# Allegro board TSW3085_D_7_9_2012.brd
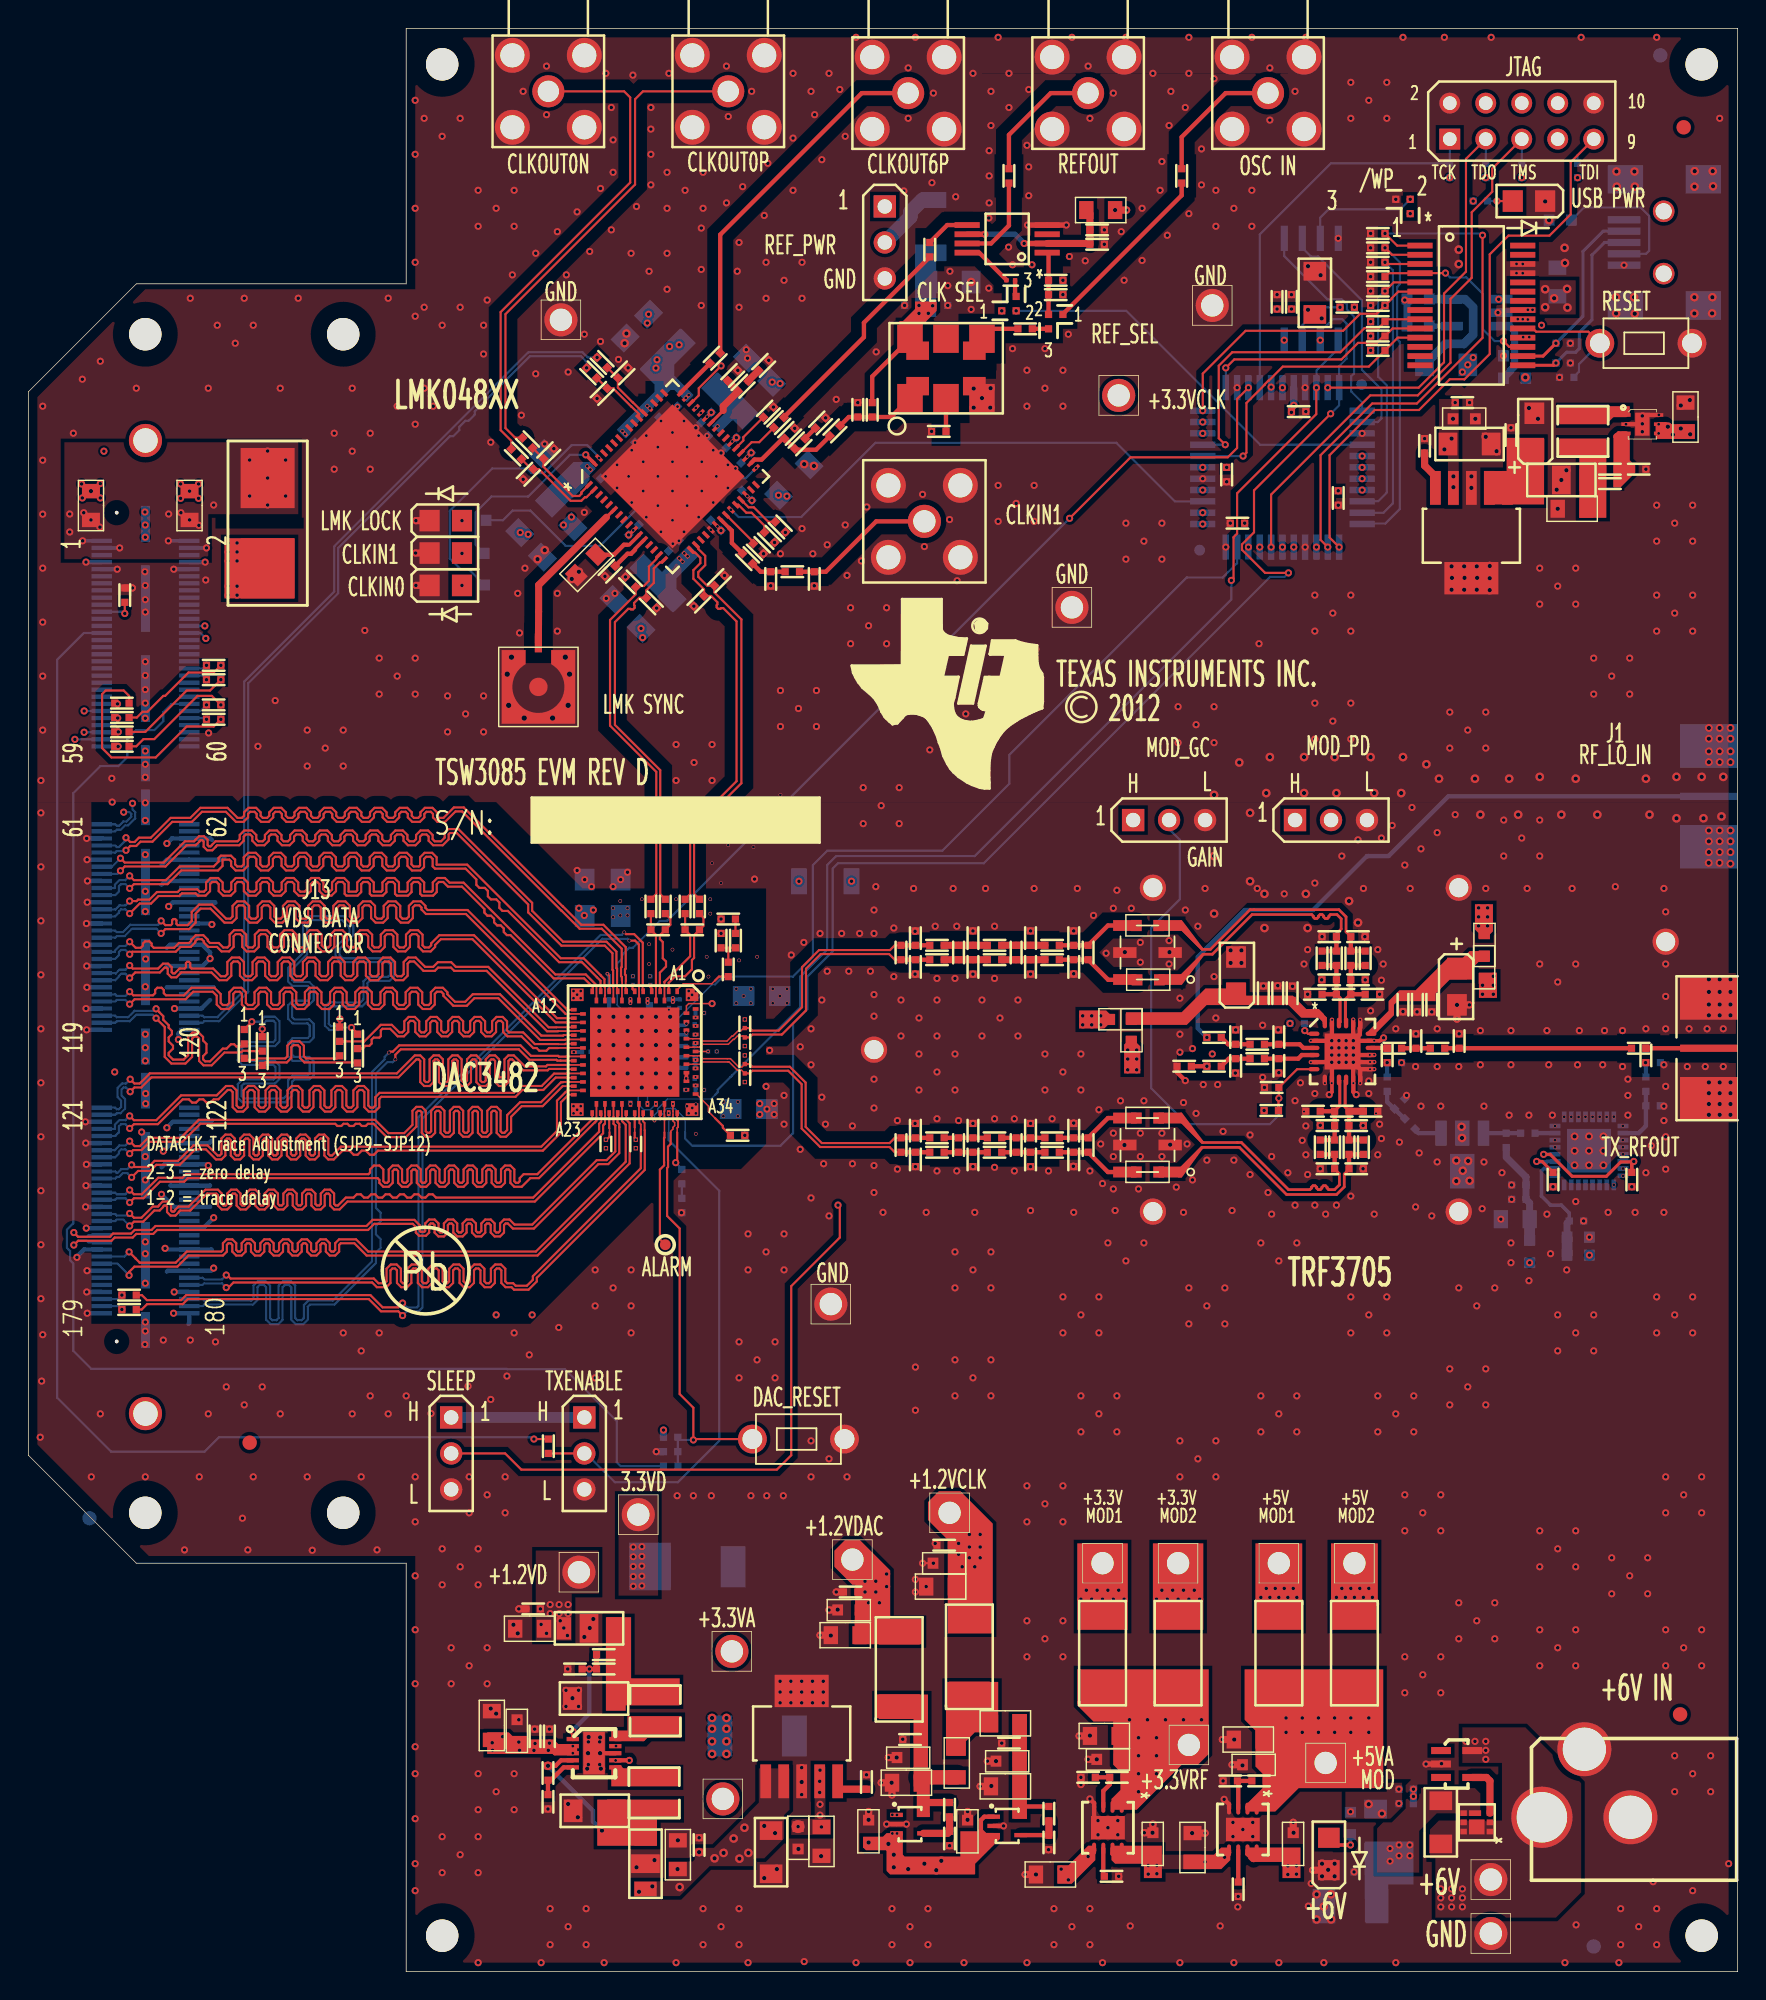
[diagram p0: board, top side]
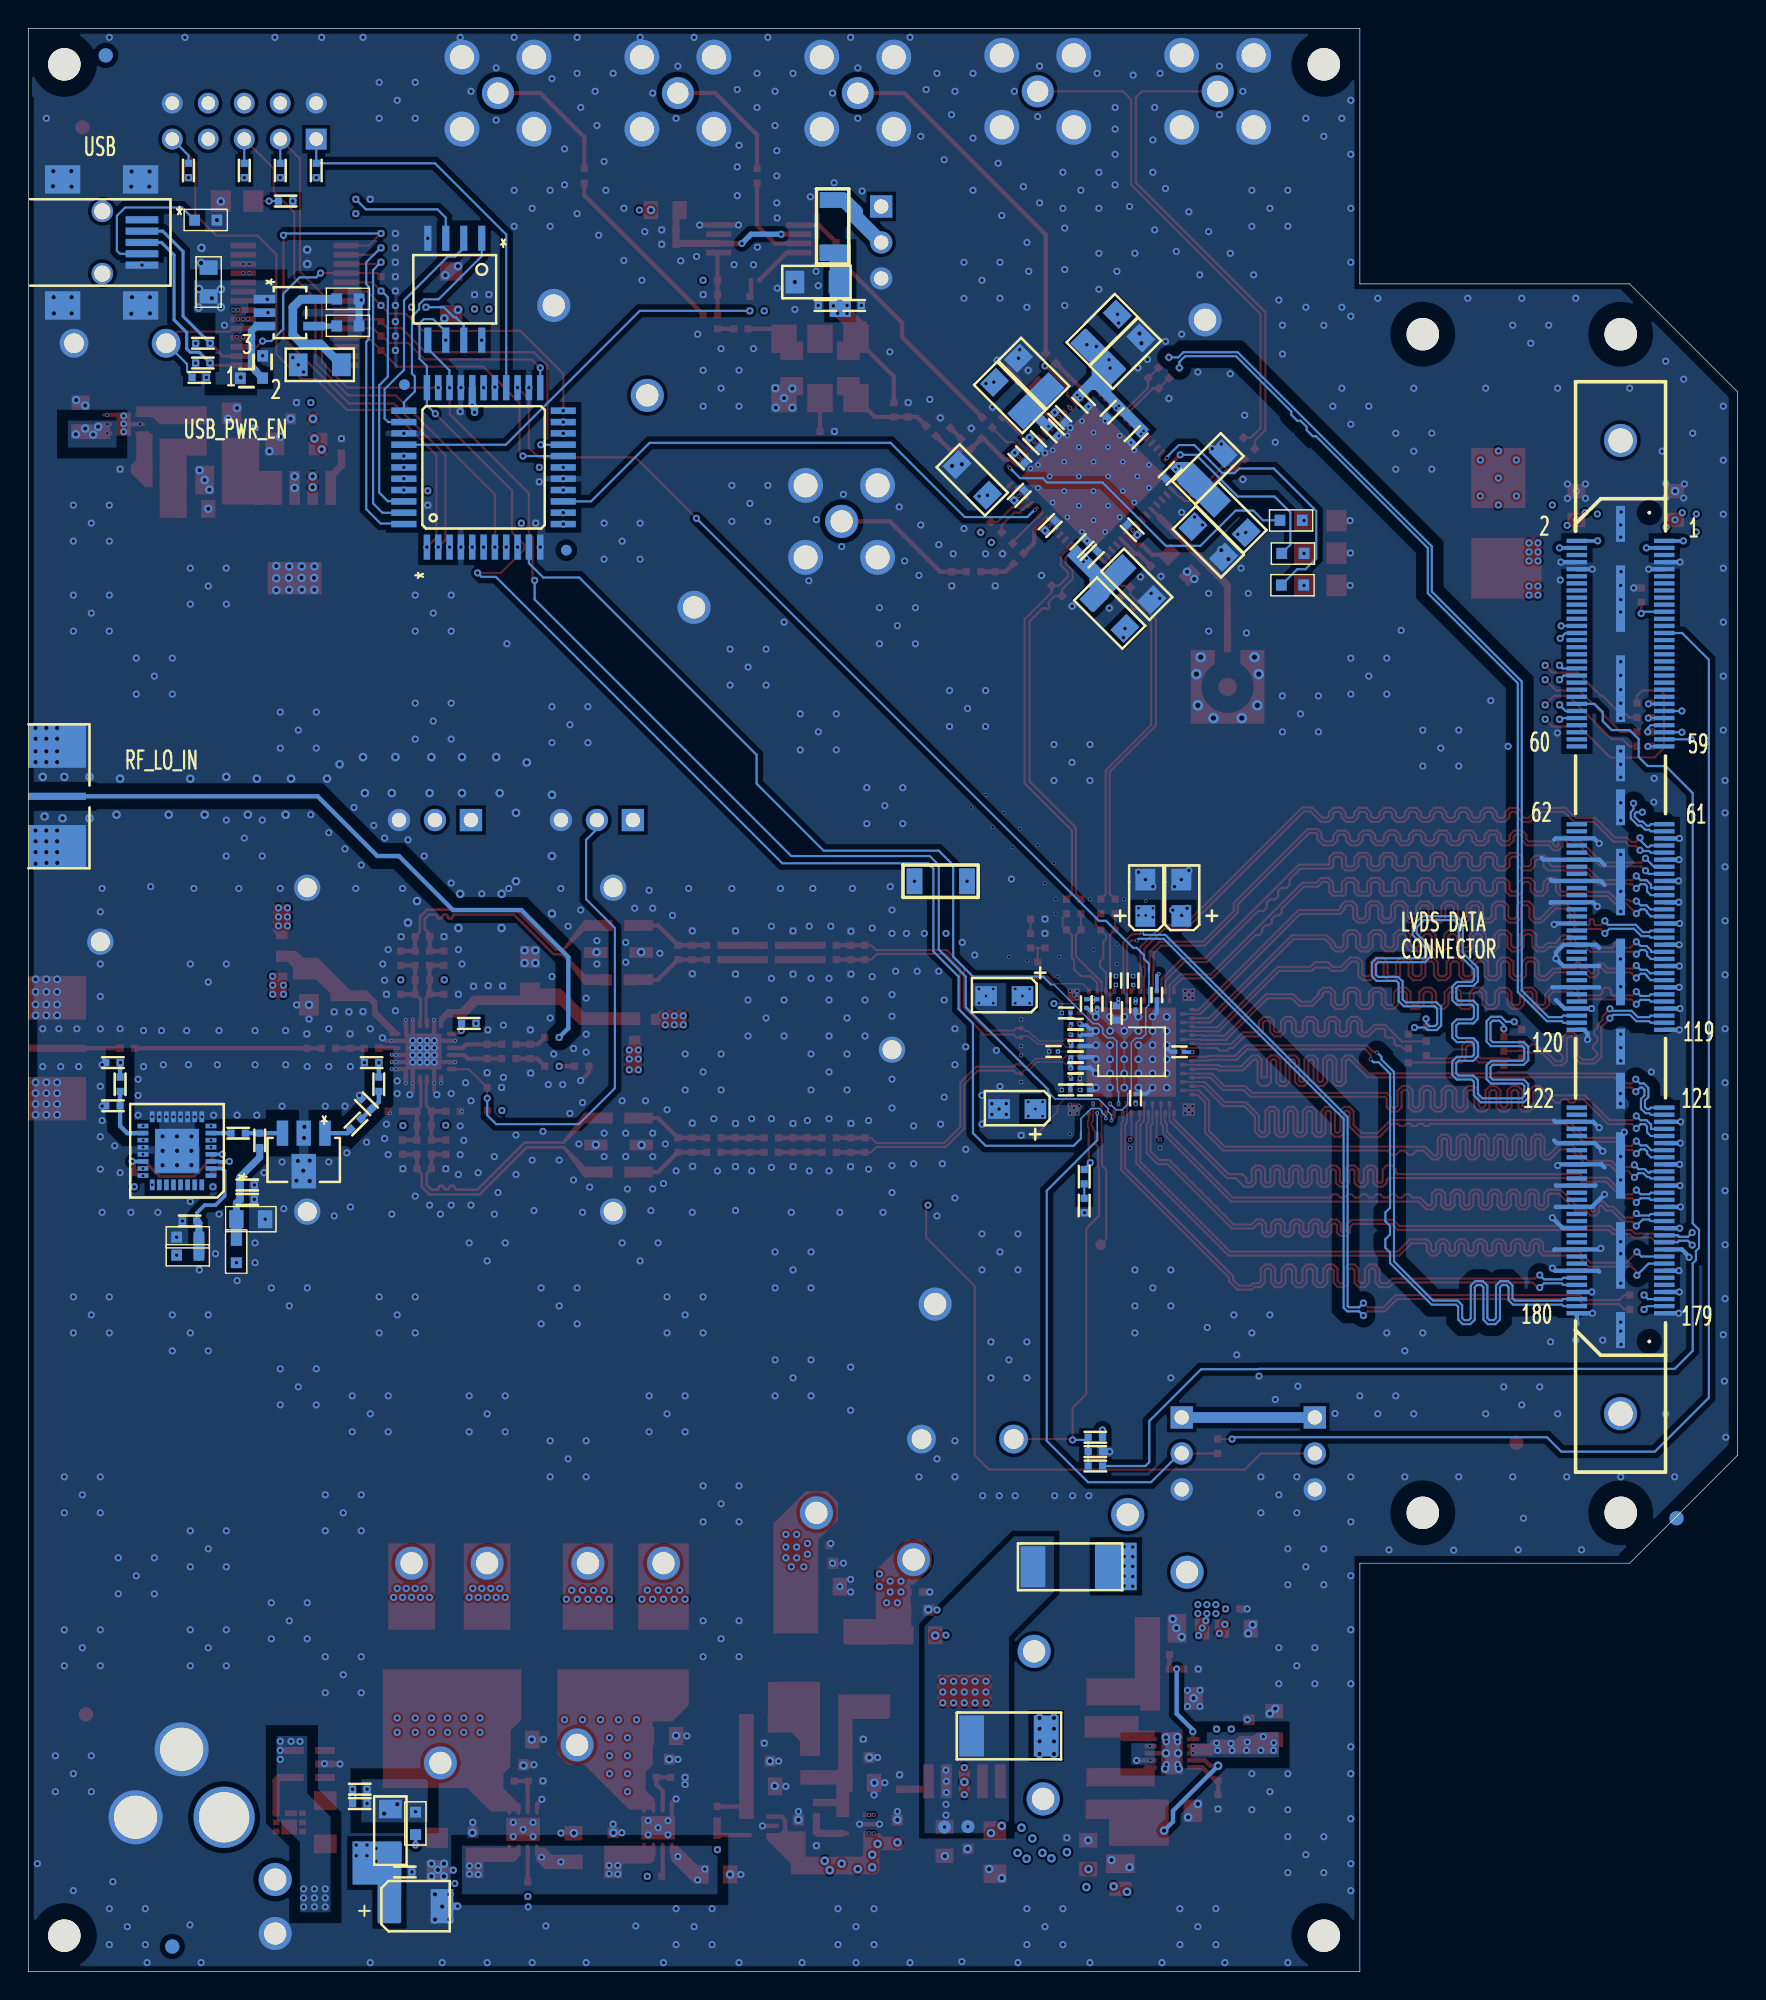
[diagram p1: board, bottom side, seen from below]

Outline 120.65 x 137.16 mm; copper layers: TOP, L2_GND, L3_PWR, L4_GND, L5_GND, L6_PWR, L7_GND, BOTTOM. Coordinates in mm from the lower left corner of the outline.
Outline path: 0,111.51 0,36.45 7.62,28.83 26.67,28.83 26.67,0 120.65,0 120.65,137.16 26.67,137.16 26.67,119.13 7.62,119.13 0,111.51

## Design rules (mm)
net group CLKIN0: nets CLKIN0N CLKIN0P
net group CLKOUT0: nets CLKOUT0N CLKOUT0P
net group CLKOUT_0: nets CLKOUT_0N CLKOUT_0P
net group DA0: nets DA0N DA0P
net group DA1: nets DA1N DA1P
net group DA2: nets DA2N DA2P
net group DA3: nets DA3N DA3P
net group DA4: nets DA4N DA4P
net group DA5: nets DA5N DA5P
net group DA6: nets DA6N DA6P
net group DA7: nets DA7N DA7P
net group DA8: nets DA8N DA8P
net group DA9: nets DA9N DA9P
net group DA10: nets DA10N DA10P
net group DA11: nets DA11N DA11P
net group DA12: nets DA12N DA12P
net group DA13: nets DA13N DA13P
net group DA14: nets DA14N DA14P
net group DA15: nets DA15N DA15P
net group DATACLK: nets DATACLKN DATACLKP
net group DATACLK-: nets DATACLK-N DATACLK-P
net group DIFFPAIR0: nets IOUTC1 IOUTC2
net group DIFFPAIR1: nets CLKOUT8N CLKOUT8P
net group DIFFPAIR2: nets TXCCLKN TXCCLKP
net group DIFFPAIR3: nets DCLKN DCLKP
net group DP2: nets IOUTB1 IOUTB2
net group DP4: nets IN-1 IP-1
net group DP5: nets FIFO_OSTR FIFO_OSTRC
net group DP7: nets DACCLK DACCLKC
net group DP8: nets IN_1 IP_1
net group DP12: nets QN-1 QP-1
net group DP14: nets QN_1 QP_1
net group DP18: nets DAC_FIFO_OSTR DAC_FIFO_OSTRC
net group FIFO_ISTR: nets FIFO_ISTRN FIFO_ISTRP
net group FPGA_CLKOUT: nets FPGA_CLKOUTN FPGA_CLKOUTP
net group PARITY: nets PARITYN PARITYP
net group PRI_DAC_CLK: nets PRI_DAC_CLKN PRI_DAC_CLKP
net group SYNC: nets SYNCN SYNCP

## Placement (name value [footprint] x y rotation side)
C1  .01uF  [0402]  46.36 75.06 270 top
C2  .01uF  [0402]  47.37 75.06 270 top
C3  .01uF  [0402]  43.94 75.31 90 top
C4  .01uF  [0402]  44.96 75.31 90 top
C5  .22uF  [0201]  46.74 63.78 180 bottom
C6  .22uF  [0201]  46.08 62.23 180 bottom
C7  0.01uF  [0603]  98.09 116.15 180 bottom
C8  4.7uF  [0603]  98.09 118.06 180 bottom
C9  10uF  [0805]  107.92 119.25 90 bottom
C13  10uF  [TANT_A]  51.77 68.86 0 bottom
C15  .22uF  [0201]  48.29 64.95 0 bottom
C17  .22uF  [0201]  47.4 67.67 0 bottom
C19  .22uF  [0201]  47.4 62.23 0 bottom
C20  .22uF  [0201]  46.74 65.33 180 bottom
C21  .22uF  [0201]  46.74 66.88 180 bottom
C22  .22uF  [0201]  46.74 64.54 180 bottom
C23  .22uF  [0201]  46.74 66.12 180 bottom
C24  .22uF  [0201]  46.74 63.02 180 bottom
C25  .22uF  [0201]  42.67 69.95 90 bottom
C26  .22uF  [0201]  41 68.94 270 bottom
C27  .22uF  [0201]  42.88 58.42 270 top
C29  .22uF  [0201]  40.77 58.42 270 top
C30  10uF  [TANT_A]  39.27 75.79 90 bottom
C34  .1uF  [0402]  49.28 74.3 180 top
C35  1000pF  [0402]  48.89 72.9 90 top
C36  .1uF  [0402]  43.84 67.54 270 bottom
C38  .22uF  [0201]  43.89 69.95 90 bottom
C40  10uF  [TANT_A]  41.81 75.79 90 bottom
C41  .22uF  [0201]  42.49 68.2 270 bottom
C42  .22uF  [0201]  42.49 61.65 90 bottom
C43  .22uF  [0201]  39.4 64.92 0 bottom
C47  1000pF  [0402]  45.21 36.7 180 bottom
C48  .1uF  [0201]  45.97 68.33 270 bottom
C49  .22uF  [0201]  45.21 68.33 270 bottom
C50  1000pF  [0402]  108.46 112.52 180 bottom
C52  .1uF  [0402]  40.97 98.76 225 top
C53  10uF  [TANT_A]  50.85 60.88 0 bottom
C59  10uF  [0805]  39.4 99.29 225 top
C60  .1uF  [0402]  52.88 109.25 225 top
C63  10uF  [1206]  65.02 119.25 0 bottom
C64  100pF  [0402]  62.23 117.6 180 bottom
C65  .1uF  [0402]  64.52 117.6 0 bottom
C72  10uF  [1206]  101.73 107.82 0 top
C75  .01uF  [0402]  101.35 110.74 0 top
C76  1uF  [0603]  101.35 109.6 0 top
C77  .1uF  [0402]  52.15 109.98 225 top
C78  .1uF  [0402]  51.44 100.53 135 top
C79  .1uF  [0402]  50.67 99.82 135 top
C80  .1uF  [0402]  42.82 101.85 45 bottom
C81  .1uF  [0402]  48.44 102.16 135 bottom
C82  .1uF  [0402]  50.57 106.76 225 bottom
C83  .1uF  [0402]  47.75 109.6 225 bottom
C84  .1uF  [0402]  50.62 104.29 135 bottom
C85  4.7uF  [0402]  49.71 108 45 bottom
C86  .1uF  [0402]  48.26 108.66 225 bottom
C87  .1uF  [0402]  40.13 105.66 315 bottom
C88  .1uF  [0402]  45.47 100 135 bottom
C89  .1uF  [0402]  42.55 108.2 315 bottom
C90  .1uF  [0402]  44.25 109.98 315 bottom
C95  47pF  [0402]  108.46 114.94 0 bottom
C96  47pF  [0402]  108.46 113.54 0 bottom
C97  .1uF  [0402]  95.12 119.63 180 top
C99  .1uF  [0402]  46.08 110.74 225 bottom
C100  .1uF  [0402]  52.98 102.06 135 top
C101  .1uF  [0402]  52.22 101.32 135 top
C102  .1uF  [0402]  46.2 100.74 135 bottom
C107  8.2pF  [0402]  49.81 112.75 45 top
C110  100pF  [0402]  105.08 55.52 180 bottom
C111  1uF  [0603]  34.49 16.99 90 top
C112  .1uF  [0402]  35.76 16.74 90 top
C113  .1uF  [0402]  76.58 6.73 0 top
C114  1uF  [0603]  79.38 9.02 90 top
C115  1uF  [0603]  76.2 14.99 180 top
C117  .1uF  [0402]  89.53 110.11 180 top
C119  .1uF  [0402]  85.39 5.69 270 top
C120  1uF  [0603]  89.28 9.02 90 top
C121  .5pF  [0402]  85.22 65.84 270 top
C122  .5pF  [0402]  88.27 65.84 270 top
C125  1.0pF  [0402]  92.96 68.99 0 top
C126  1.0pF  [0402]  92.84 60.73 0 top
C127  1500pF  [0402]  50.55 111.99 45 top
C128  10uF  [1206]  37.36 100.91 225 bottom
C131  .5pF  [0402]  88.27 64.06 90 top
C132  .5pF  [0402]  85.22 64.06 90 top
C133  10uF  [0805]  45.85 8.25 90 top
C134  10uF  [0805]  35.38 24.21 180 top
C135  .1uF  [0402]  84.58 105.79 90 top
C138  .1uF  [0402]  85.47 102.23 0 top
C139  .1uF  [0402]  92.46 104.14 90 top
C143  10uF  [0805]  4.42 103.48 90 top
C144  10uF  [0805]  11.38 103.48 90 top
C145  10uF  [0805]  55.98 9.19 270 top
C146  10uF  [0805]  61.98 13.34 180 top
C147  10uF  [0805]  57.66 23.75 180 top
C148  10uF  [0805]  64.39 27.18 180 top
C149  10uF  [0805]  68.96 13.08 180 top
C150  10uF  [0805]  72.14 6.86 180 top
C152  47uF  [TANT_B]  93.32 4.62 180 bottom
C153  .1uF  [0402]  93.95 7.04 180 bottom
C154  1uF  [0402]  97.38 11.86 0 bottom
C155  .01uF  [0402]  97.38 12.88 0 bottom
C156  .2pF  [0402]  97.94 65.56 270 top
C157  .5pF  [0402]  100.99 65.56 270 top
C161  10uF  [0805]  32.72 17.37 90 top
C162  .01uF  [0402]  59.16 13.51 90 top
C163  2.2uF  [1206]  52.43 8.43 270 top
C164  1uF  [0603]  54.33 9.45 270 top
C165  22uF  [1206]  39.98 11.35 180 top
C166  33pF  [0402]  40.49 21.36 180 top
C167  22uF  [1206]  39.93 19.28 180 top
C169  2.2uF  [0603]  59.31 9.91 90 top
C170  1uF  [0603]  57.91 25.53 180 top
C171  10uF  [0805]  75.95 16.64 180 top
C172  10uF  [0805]  82.17 8.76 90 top
C173  10uF  [0805]  86.11 16.38 180 top
C174  1uF  [0603]  86.49 14.61 180 top
C175  1000pF  [0402]  109.4 52.98 0 bottom
C176  1uF  [0603]  109.4 51.84 0 bottom
C177  .1uF  [0402]  54.56 107.92 45 top
C178  10uF  [1206]  54.03 105.28 45 bottom
C179  10uF  [1206]  37.39 106.07 135 bottom
C180  10uF  [1206]  43.21 114.22 135 bottom
C181  10uF  [1206]  42.42 97.92 225 bottom
C182  .1uF  [0402]  89.15 117.98 90 top
C184  3.3pF  [0402]  65.66 71.81 270 top
C185  3.3pF  [0402]  61.59 71.81 270 top
C186  3.3pF  [0402]  69.72 71.81 270 top
C187  100pF  [0402]  87.88 62.41 0 top
C190  3.3pF  [0402]  74.8 71.81 270 top
C191  CAP NP_1  [0402]  62.61 70.79 270 top
C192  CAP NP_1  [0402]  66.68 70.79 270 top
C193  CAP NP_1  [0402]  70.74 70.79 270 top
C194  CAP NP_1  [0402]  73.79 70.79 270 top
C195  CAP NP_1  [0402]  73.79 72.82 270 top
C196  CAP NP_1  [0402]  62.61 72.82 270 top
C197  CAP NP_1  [0402]  66.68 72.82 270 top
C198  CAP NP_1  [0402]  70.74 72.82 270 top
C199  CAP NP_1  [0402]  73.79 57.45 90 top
C200  CAP NP_1  [0402]  66.68 57.45 90 top
C204  3.3pF  [0402]  61.59 58.47 90 top
C205  3.3pF  [0402]  65.66 58.47 90 top
C206  3.3pF  [0402]  69.72 58.47 90 top
C214  1uF  [0402]  94.36 71.4 270 top
C215  .01uF  [0402]  98.55 107.82 90 top
C216  CAP NP_1  [0402]  62.61 57.45 90 top
C217  CAP NP_1  [0402]  70.74 57.45 90 top
C218  CAP NP_1  [0402]  73.79 59.49 90 top
C219  CAP NP_1  [0402]  62.61 59.49 90 top
C220  CAP NP_1  [0402]  66.68 59.49 90 top
C221  CAP NP_1  [0402]  70.74 59.49 90 top
C222  3.3pF  [0402]  74.8 58.47 90 top
C227  1uF  [0402]  91.31 71.4 270 top
C228  1uF  [0402]  94.23 58.32 90 top
C229  1uF  [0402]  91.19 58.32 90 top
C233  .01uF  [0402]  35.51 25.6 180 top
C234  .01uF  [0402]  47.35 9.07 90 top
C237  .01uF  [0402]  36.78 16.74 90 top
C238  1uF  [0603]  64.64 28.83 180 top
C240  2.2uF  [0603]  66.29 9.91 90 top
C242  .01uF  [0402]  64.52 30.1 180 top
C243  .01uF  [0402]  57.91 26.8 180 top
C244  1uF  [0603]  62.1 15.11 180 top
C245  .01uF  [0402]  62.1 16.38 180 top
C246  1uF  [0603]  69.09 14.86 180 top
C247  .01uF  [0402]  69.09 16.13 180 top
C249  20pF  [0402]  105.71 59.18 180 bottom
C250  .1uF  [0402]  88.14 117.98 90 top
C251  .1uF  [0402]  105.08 54.51 180 bottom
C252  3.3pF  [0402]  89.2 69.19 90 top
C253  .1uF  [0402]  88.19 69.19 90 top
C254  .1uF  [0402]  98.04 68.12 270 top
C255  3.3pF  [0402]  97.03 68.12 270 top
C256  2.2uF  [0805]  104.95 53.11 180 bottom
C257  20pF  [0402]  97.43 59.92 135 bottom
C258  6.8pF  [0402]  96.55 65.18 0 top
C259  47pF  [0402]  83.82 63.91 0 top
C260  47pF  [0402]  83.82 65.94 0 top
C288  1000pF  [0402]  87.17 69.19 90 top
C289  1000pF  [0402]  99.06 68.12 270 top
C290  4.7uF  [TANT_A]  85.24 70.33 90 top
C291  4.7uF  [TANT_A]  100.84 69.52 270 top
C298  10uF  [1206]  49.68 112.8 45 bottom
C299  22pF  [0402]  111.76 106.05 0 top
C300  .1uF  [0402]  53.82 108.66 45 top
C301  .1uF  [0402]  81.41 126.62 270 top
C302  .01uF  [0402]  75.56 121.92 0 top
C303  .1uF  [0402]  75.56 122.94 0 top
C304  10uF  [0805]  116.97 109.73 90 top
C305  10uF  [0805]  108.97 103.25 180 top
C306  2.2uF  [TANT_A]  106.3 108.71 90 top
C307  .01uF  [0402]  104.65 108.59 90 top
C312  10uF  [1206]  90.81 118.49 90 top
C337  .1uF  [0402]  50.19 59.03 0 top
D1  LED GREEN  [LED_0805]  29.46 97.84 180 top
D2  LED BLUE  [LED_0805]  91.8 8.31 270 top
D3  LED AMBER  [LED_0805]  105.92 124.97 0 top
D4  LED GREEN  [LED_0805]  29.46 102.41 180 top
D5  LED GREEN  [LED_0805]  29.46 100.13 180 top
F1  1 AMP FUSE  [NANO_SMF]  16.89 102.23 90 top
F2  2 AMP 63V FAST SMD  [1206]  99.69 10.54 90 top
FB1  1K OHM @ 100MHz  [1806]  56.25 76.96 180 bottom
FB2  1K OHM @ 100MHz  [1806]  63.88 123.19 90 bottom
FB8  31 OHM @ 100MHz  [0805]  75.69 124.33 0 top
FB10  68 OHM @ 100MHz  [1206]  44.32 95.89 225 bottom
FB12  68 OHM @ 100MHz  [1206]  51.38 111.1 45 bottom
FB18  68 OHM @ 100MHz  [1206]  44.86 115.9 135 bottom
FB19  68 OHM @ 100MHz  [1206]  35.76 102.64 225 bottom
FB20  68 OHM @ 100MHz  [1206]  95.1 9.96 270 bottom
FB22  1K OHM @ 100MHz  [1810]  47.12 28.57 180 bottom
FB23  600 OHMS @ 100MHz  [0603]  109.4 50.57 0 bottom
FB24  1K OHM @ 100MHz  [1810]  51.44 16.64 180 bottom
FB26  120 OHM @ 100MHz  [1206]  100.08 113.41 0 bottom
FB28  27uF  [1206_BEAD_NFM31P]  108.2 105.28 180 top
FB30  27uF  [1206_BEAD_NFM31P]  39.57 24.23 180 top
FB31  27uF  [1206_BEAD_NFM31P]  43.56 7.62 270 top
FB33  1K OHM @ 100MHz  [1810]  75.82 22.48 90 top
FB34  1K OHM @ 100MHz  [1810]  61.47 21.34 90 top
FB35  1K OHM @ 100MHz  [1810]  66.42 22.22 90 top
FB36  1K OHM @ 100MHz  [1810]  81.15 22.48 90 top
FB39  1K OHM @ 100MHz  [1810]  88.27 22.48 270 top
FB40  1K OHM @ 100MHz  [1810]  93.6 22.48 270 top
J1  SMA END LAUNCH  [SMA_SMEL_DUAL_PSF-S01_250X215]  120.65 82.96 90 bottom
J2  SMA THRU HOLE R/A  [SMA_THRT_276X276]  49.4 132.72 90 top
J3  SMA THRU HOLE R/A  [SMA_THRT_276X276]  36.7 132.72 90 top
J4  CONN JACK PWR  [CON_RAPC722_JACK_THVT_3]  109.96 10.9 90 top
J5  SMA THRU HOLE R/A  [SMA_THRT_276X276]  62.1 132.59 90 top
J6  SMA THRU HOLE R/A  [SMA_THRT_276X276]  74.8 132.59 90 top
J7  SMA END LAUNCH  [SMA_SMEL_DUAL_PSF-S01_250X215]  120.65 65.18 270 top
J10  SMP_PCB_SMT  [SMP_B120]  36 90.68 180 top
J11  SMA THRU HOLE R/A  [SMA_THRT_276X276]  87.5 132.59 90 top
J12  SMA THRU HOLE  [SMA_THVT_320X320]  63.25 102.36 90 top
J13  HEADER, SMT, 180POS, HS GND PLANE  [CON_SMVT_180POS_QTH_SAMTEC_RT1]  6.24 102.95 270 bottom
J14  USB_MINI_AB  [CON_SMRT_USBMNE20_F]  116.08 122.05 180 bottom
J15  HTSW-105-07-G-D  [HDR_THVT_2X5_100_M]  100.33 129.34 90 top
JP1  HEADER, 3POS  [HDR_THVT_1X3_100_M]  77.98 81.28 90 top
JP2  HEADER, 3POS  [HDR_THVT_1X3_100_M]  39.24 39.12 0 top
JP3  HEADER, 3POS  [HDR_THVT_1X3_100_M]  29.85 39.12 0 top
JP4  HEADER, 3POS  [HDR_THVT_1X3_100_M]  60.45 124.59 0 top
JP5  HEADER, 3POS  [HDR_THVT_1X3_100_M]  89.41 81.28 90 top
L1  33nH  [0402]  64.01 57.84 180 top
L2  33nH  [0402]  64.01 58.85 180 top
L3  33nH  [0402]  64.01 72.44 180 top
L4  33nH  [0402]  64.01 71.42 180 top
L5  5.6nH  [0402]  104.31 58.8 90 bottom
L7  2.2uH  [LPS3015]  109.73 108.71 270 top
L25  2.2uH  [LPS3015]  44.17 12.62 270 top
L26  2.2uH  [LPS3015]  44.25 18.41 90 top
NOREF  -  [unnamed]  29.21 134.62 0 top
NOREF#2  -  [unnamed]  29.21 2.54 0 top
NOREF#3  -  [unnamed]  22.23 115.57 0 top
NOREF#4  -  [unnamed]  8.26 115.57 0 top
NOREF#5  -  [#2]  29.21 2.54 90 top
NOREF#6  -  [#2]  -131.7 -62.23 0 top
NOREF#7  -  [unnamed]  22.23 32.38 0 top
NOREF#8  -  [#2]  31.29 78.09 0 top
NOREF#9  -  [#2]  59.69 76.5 0 top
NOREF#10  -  [#2]  -130.81 -63.5 0 top
NOREF#11  -  [#2]  100.97 53.64 90 top
NOREF#12  -  [#2]  40.51 69.47 0 top
NOREF#13  -  [#2]  52.3 53.64 90 top
NOREF#14  -  [#2]  79.38 53.64 90 top
NOREF#15  -  [#2]  79.38 53.64 90 top
NOREF#16  -  [#2]  29.21 2.54 90 top
NOREF#17  -  [#2]  79.38 53.64 90 top
NOREF#18  -  [unnamed]  118.11 134.62 0 top
NOREF#19  -  [#2]  131.11 18.39 0 top
NOREF#20  -  [#2]  59.69 76.5 0 top
NOREF#21  -  [#2]  100.97 53.64 90 top
NOREF#22  -  [unnamed#3]  15.62 37.34 0 top
NOREF#23  -  [#2]  60.59 70.48 0 top
NOREF#24  -  [#2]  0 36.45 0 top
NOREF#25  -  [#2]  58.93 57.15 0 top
NOREF#26  -  [#2]  116.87 63.98 90 top
NOREF#27  -  [#2]  -53.34 -14.73 0 top
NOREF#28  -  [#2]  3.31 114.82 0 top
NOREF#29  -  [#2]  116.59 73.41 0 top
NOREF#30  -  [#2]  26.67 0 90 top
NOREF#31  -  [#2]  120.65 0 90 top
NOREF#32  -  [unnamed]  8.26 32.38 0 top
NOREF#33  -  [unnamed#3]  116.84 130.18 0 top
NOREF#34  -  [#2]  89.88 39.31 0 top
NOREF#35  -  [#2]  79.38 53.64 90 top
NOREF#36  -  [#2]  29.21 2.54 0 top
NOREF#37  -  [#2]  59.69 76.5 0 top
NOREF#38  -  [#2]  26.67 0 0 top
NOREF#39  -  [unnamed]  118.11 2.54 0 top
NOREF#40  -  [#2]  100.97 53.64 90 top
NOREF#41  -  [#2]  -116.84 419.86 0 top
NOREF#42  -  [#2]  742.85 139.24 0 top
NOREF#43  -  [unnamed#3]  116.59 18.16 0 top
NOREF#44  -  [#2]  79.38 53.64 90 top
NOREF#45  -  [unnamed#3]  4.32 32 180 bottom
NOREF#46  -  [unnamed#3]  115.19 135.25 180 bottom
NOREF#47  -  [unnamed#3]  110.49 1.78 180 bottom
PP1  PROBE POINT  [PROBE_POINT_30PAD]  44.96 51.31 0 top
Q1  CSD17313Q2  [SON_8_2MMX2MM_0P65MM]  102.24 10.54 90 top
R1  0  [0402]  6.73 89.54 0 top
R2  0  [0402]  6.73 88.52 0 top
R3  0  [0402]  6.73 87.5 0 top
R4  0  [0402]  6.73 86.49 0 top
R5  100  [0402]  46.99 73.53 0 top
R6  0  [0402]  6.81 97.28 90 top
R7  0  [0402]  45.21 35.69 180 bottom
R8  750  [0603]  31.42 97.87 0 bottom
R9  750  [0603]  31.39 100.1 0 bottom
R10  330K  [0402]  65.02 9.53 90 top
R11  750  [0603]  31.52 102.44 0 bottom
R12  330K  [0402]  72.03 9.25 90 top
R15  100  [0402]  44.32 73.53 180 top
R16  4.75K  [0402]  95.12 122.68 180 top
R17  4.75K  [0402]  95.12 118.62 180 top
R18  0  [0402]  36.7 37.21 90 top
R19  4.75K  [0402]  95.12 120.65 180 top
R20  4.75K  [0402]  95.12 114.43 180 top
R21  4.75K  [0402]  95.12 121.67 180 top
R22  4.75K  [0402]  95.12 116.46 180 top
R23  4.75K  [0402]  95.12 115.44 180 top
R24  4.75K  [0402]  95.12 117.6 180 top
R25  0  [0402]  12.95 92.2 180 top
R26  0  [0402]  12.95 91.19 180 top
R27  0  [0402]  12.95 88.39 180 top
R28  0  [0402]  12.95 89.41 180 top
R40  3.01K  [0402]  102.62 124.97 0 bottom
R42  49.9  [0201]  50.57 63.09 270 top
R43  1K  [0402]  49.91 72.9 90 top
R44  1.27K  [0402]  46.13 55.98 270 bottom
R45  10  [0402]  46.13 53.95 270 bottom
R46  1K  [0402]  45.21 37.72 180 bottom
R48  30.1  [0402]  63.63 121.67 90 top
R49  30.1  [0402]  69.22 126.62 270 top
R50  0  [0402]  48.39 113.79 225 top
R51  240  [0402]  44.07 96.52 315 top
R52  240  [0402]  42.42 98.17 135 top
R53  30.1  [0201]  69.34 119.38 180 top
R54  22.1  [0402]  70.48 115.95 0 top
R55  240  [0402]  42.06 112.93 45 top
R56  240  [0402]  35.2 105.6 225 top
R57  240  [0402]  36.82 107.22 45 top
R58  0  [0402]  35.33 107.81 315 top
R59  0  [0402]  34.54 107.02 315 top
R60  240  [0402]  47.24 96.65 225 top
R61  1K  [0402]  59.56 110.11 270 top
R62  1K  [0402]  58.55 110.11 270 top
R63  18  [0402]  53.8 98.81 180 top
R70  10K  [0402]  72.39 119.38 180 top
R72  10K  [0402]  72.64 118.36 0 top
R88  0  [0603]  77.85 66.45 270 top
R89  15K  [0402]  51.99 113.46 45 top
R90  10K  [0402]  56.01 109.4 45 top
R91  240  [0402]  40.41 111.3 225 top
R92  240  [0402]  48.87 98.27 45 top
R93  0  [0402]  114.55 61.11 180 bottom
R94  0  [0402]  114.17 62.76 90 bottom
R95  150K  [0402]  113.54 106.05 180 top
R96  0  [0603]  102.77 70.89 90 top
R99  49.9  [0201]  50.57 64.36 90 top
R100  49.9  [0201]  50.57 66.9 90 top
R101  49.9  [0201]  50.57 65.63 270 top
R103  0  [0402]  95.91 62.51 270 bottom
R104  750K  [0402]  111.51 105.03 180 top
R105  270  [0402]  52.4 98.17 270 top
R106  0  [0402]  114.55 64.16 180 bottom
R107  4.75K  [0402]  107.62 56.03 90 top
R108  0  [0402]  113.18 56.03 90 top
R115  0  [0603]  102.77 72.47 270 top
R117  0  [0603]  108.13 123.62 180 bottom
R118  0  [0603]  77.09 67.21 0 top
R120  4.75K  [0402]  92.96 117.48 180 top
R121  10K  [0402]  102.87 127 270 bottom
R122  1K  [0402]  100.33 127 270 bottom
R125  10K  [0402]  105.41 127 270 bottom
R127  0  [0805]  68.96 17.53 180 top
R128  0  [0805]  65.53 14.73 270 top
R129  10K  [0402]  109.35 127 270 bottom
R130  270  [0402]  55.47 98.17 270 top
R133  0  [0402]  49.4 70.61 270 top
R136  0  [0402]  96.29 64.16 180 bottom
R137  0  [0402]  96.7 61.16 225 bottom
R143  10K  [0603]  93.32 10.46 90 bottom
R148  750K  [0402]  36.68 14.15 90 top
R150  191K  [0402]  40.74 22.38 0 top
R151  150K  [0402]  36.68 12.12 90 top
R153  182K  [0402]  38.71 21.36 0 top
R157  31.6K  [0402]  76.96 13.72 0 top
R159  10K  [0402]  74.93 13.72 0 top
R161  0  [0402]  114.17 64.54 270 top
R163  0  [0402]  95.91 64.54 270 top
R165  0  [0402]  113.54 65.18 180 top
R167  0  [0402]  99.34 65.18 180 top
R169  0  [0402]  86.87 65.46 0 top
R171  10K  [0402]  84.96 13.46 0 top
R174  0  [0402]  86.87 64.44 0 top
R175  0  [0402]  7.24 47.75 0 top
R176  53.6K  [0402]  87 13.46 0 top
R177  0  [0402]  7.24 46.74 0 top
R181  0  [0402]  87.6 60.78 180 top
R185  0  [0402]  89.43 66.93 180 bottom
R198  49.9  [0402]  93.98 73.05 0 top
R199  49.9  [0402]  91.69 73.05 180 top
R200  49.9  [0402]  93.85 56.67 0 top
R201  49.9  [0402]  91.57 56.67 180 top
R206  49.9  [0402]  95 68.99 0 top
R207  49.9  [0402]  90.93 68.99 0 top
R208  0  [0402]  93.34 71.4 270 top
R209  2.74K  [0402]  93.73 70 180 top
R210  0  [0402]  92.33 71.4 270 top
R211  2.74K  [0402]  91.95 70 0 top
R212  0  [0402]  93.22 58.32 90 top
R213  2.74K  [0402]  93.6 59.71 180 top
R214  0  [0402]  92.2 58.32 90 top
R215  2.74K  [0402]  91.82 59.71 0 top
R221  174K  [0402]  72.03 11.28 90 top
R225  49.9  [0402]  90.81 60.73 0 top
R226  49.9  [0402]  94.87 60.73 0 top
R257  174K  [0402]  65.02 11.56 90 top
R273  0  [0402]  57.02 108.84 45 top
R274  0  [0402]  64.39 108.71 0 top
R275  0  [0402]  40.41 113.67 135 top
R276  0  [0402]  39.67 112.93 135 top
R277  0  [0402]  68.33 72.44 0 top
R278  0  [0402]  68.33 71.42 0 top
R279  0  [0402]  68.33 58.85 0 top
R280  0  [0402]  68.33 57.84 0 top
R289  0  [0603]  78.99 73.84 0 top
R290  0  [0603]  79.04 70 0 top
R291  0  [0603]  78.99 56.44 0 top
R292  0  [0603]  78.99 60.25 0 top
R293  0  [0603]  105.97 50.82 90 bottom
R296  0  [0402]  72.39 72.44 0 top
R297  0  [0402]  72.39 71.42 0 top
R302  0  [0402]  72.39 57.84 0 top
R303  0  [0402]  72.39 58.85 0 top
R313  49.9  [0402]  81.46 63.91 180 top
SH1  RF SHIELD  [MFG053_PTH]  59.69 65.07 0 top
SH2  RF SHIELD  [MFG053_PTH]  79.38 76.5 0 top
SH3  RF SHIELD  [MFG053_PTH]  100.97 76.5 0 top
SH4  RF SHIELD  [MFG053_PTH]  79.38 53.64 0 top
SH5  RF SHIELD  [MFG053_PTH]  115.57 72.69 0 top
SH6  RF SHIELD  [MFG053_PTH]  100.97 53.64 0 top
SJP1  SOLDER JUMPER, 0603  [JUMPER_SMD_3POS_0402]  23.24 65.15 90 top
SJP2  SOLDER JUMPER, 0402  [SMD_JUMPER_L_0402]  97.54 124.59 90 top
SJP3  SOLDER JUMPER, 0603  [JUMPER_SMD_L_0603]  104.62 112.47 180 bottom
SJP4  SOLDER JUMPER, 0402  [SMD_JUMPER_L_0402]  69.22 117.22 0 top
SJP5  SOLDER JUMPER, 0402  [SMD_JUMPER_L_0402]  72.52 116.97 180 top
SJP6  SOLDER JUMPER, 0603  [JUMPER_SMD_3POS_0402]  21.97 65.66 90 top
SJP7  SOLDER JUMPER, 0603  [JUMPER_SMD_3POS_0402]  15.24 65.48 90 top
SJP8  SOLDER JUMPER, 0603  [JUMPER_SMD_3POS_0402]  16.51 64.97 90 top
SW1  SW PUSHBUTTON  [SW_RESET_PTS635]  54.36 37.59 180 top
SW2  SW PUSHBUTTON  [SW_RESET_PTS635]  114.17 114.94 180 top
T1  TC1-1-13M  [XFMR_MINICIRCUITS_AT224_1]  78.99 71.93 0 top
T2  TC1-1-13M  [XFMR_MINICIRCUITS_AT224_1]  78.99 58.34 0 top
TP1  TEST POINT, RED  [TESTPOINT_62DIA]  93.6 28.83 0 top
TP2  TEST POINT, RED  [TESTPOINT_62DIA]  88.27 28.83 0 top
TP3  TEST POINT, RED  [TESTPOINT_62DIA]  91.57 14.73 0 top
TP4  TEST POINT, RED  [TESTPOINT_62DIA]  81.91 16 0 top
TP5  TEST POINT, RED  [TESTPOINT_62DIA]  81.15 28.83 0 top
TP6  TEST POINT, BLK  [TESTPOINT_62DIA]  56.64 47.12 0 top
TP7  TEST POINT, BLK  [TESTPOINT_62DIA]  37.59 116.59 270 top
TP8  TEST POINT, BLK  [TESTPOINT_62DIA]  73.66 96.29 0 top
TP9  TEST POINT, BLK  [TESTPOINT_62DIA]  83.57 117.6 0 top
TP10  TEST POINT, RED  [TESTPOINT_62DIA]  75.82 28.83 0 top
TP12  TEST POINT, RED  [TESTPOINT_62DIA]  103.23 6.5 90 top
TP13  TEST POINT, BLK  [TESTPOINT_62DIA]  103.23 2.69 90 top
TP15  TEST POINT, RED  [TESTPOINT_62DIA]  38.86 28.19 90 top
TP16  TEST POINT, RED  [TESTPOINT_62DIA]  49.66 22.61 0 top
TP17  TEST POINT, RED  [TESTPOINT_62DIA]  76.96 111.25 180 top
TP18  TEST POINT, RED  [TESTPOINT_62DIA]  58.17 29.08 0 top
TP19  TEST POINT, RED  [TESTPOINT_62DIA]  65.02 32.38 0 top
TP20  TEST POINT, RED  [TESTPOINT_62DIA]  49.02 12.19 0 top
TP21  TEST POINT, RED  [TESTPOINT_62DIA]  43.05 32.26 0 top
U1  DAC3482  [WQFN_88_354X354_0P60MM]  42.8 64.9 270 top
U2  TPS62290  [SON_DRV_6]  113.92 109.22 0 top
U3  FT245RL  [SSOP_28_413X220_26]  101.85 117.6 0 top
U4  EPM3064A  [TQFP_44_39X39_32]  88.52 106.17 90 bottom
U5  25AA512  [SO_8_210X212_50]  90.55 118.75 0 bottom
U6  LP2985-50  [SOT_5_120X69_37]  102.24 117.09 270 bottom
U7  PE43701  [QFN_32_197X197_20_PWRPAD]  110.16 57.94 0 bottom
U8  MGA-30689  [SOT_89_4321]  101.21 57.29 0 bottom
U11  TPS62420  [SON_DRC_10]  39.93 15.42 0 top
U12  TPS79633  [SOT_223_6_TG]  55.22 16.81 0 top
U13  TPS71701  [SC70_DCK_G5]  62.23 10.41 0 top
U14  TPS7A8001DRB  [SON_8_124X124_PWRPAD_DRB]  76.2 10.16 270 top
U15  TPS79633  [SOT_223_6_TG]  101.22 101.35 180 top
U16  LMK04806B  [QFN_64_360X360_0P50MM_SQA64]  45.47 105.54 45 top
U18  TPS7A8001DRB  [SON_8_124X124_PWRPAD_DRB]  85.72 10.03 270 top
U21  TPS2400  [DBV5]  100.81 14.66 0 top
U22  TPS71701  [SC70_DCK_G5]  69.09 10.29 0 top
U23  TRF3705  [QFN_24_163X163_0P50MM_PWRPAD]  92.76 64.95 0 top
U26  CDCV304PW  [TSSOP_8_177X122_26]  69.09 122.3 180 top
Y1  10.000MHz  [OSC_6_SM_295X205_100_CUSTOM]  64.77 113.16 0 top

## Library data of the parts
C1-C4 C35 C47 C64 C110 C127 C175 C249 C257 C288 C289 C302 = CAP NP_0: tolerance: 5%
C5 C6 C15 C17 C19-C27 C29 C38 C41-C43 C49 = CAP NP_0: tolerance: 20%
C7 = CAP_0603_0.01uF
C8 = CAP_0603_4.7uF
C9 = CAP_0805_10uF_10V: tolerance: 10%
C13 C30 C40 C53 = CAP POL-B_10uF_10V
C34 C36 C65 C76 C107 C176 C177 C182 C214 C227-C229 C250 C251 C253 C254 C256 C300 C301 C303 C337 = CAP NP_0: tolerance: 10%
C48 = CAP0402: tolerance: -20%/+80%
C50 C155 = CAP NP_1: tolerance: 5%
C52 C60 C77-C84 C86-C90 C99-C102 C117 C135 C138 C139 = CAPACITOR_NP_1: tolerance: 10%
C59 C72 C111 C114 C115 C120 C128 C174 C178-C181 C298 = CAP NP_2: tolerance: 10%
C63 C97 C154 C164 C165 C167 C169 C170 C238 C240 C244 C246 C312 = CAP NP_1: tolerance: 10%
C75 = CAP0201: tolerance: 5%
C85 = CAPACITOR_NP_1: tolerance: 20%
C95 C96 = CAP0603: tolerance: 2%
C112 C113 C119 C133 C134 C143-C149 C153 C161 = CAP NP: tolerance: 10%
C121 C122 C131 C132 = CAP NP_2: tolerance: .25pF
C125 C126 = CAP_0402
C150 C171-C173 C304 C305 = CAP0201: tolerance: 10%
C152 = CAP POL: tolerance: 10%
C156 C157 = CAP NP_2: tolerance: .1pF
C162 C215 C233 C234 C237 C242 C243 C245 C247 C307 = CAPACITOR_NP_4: tolerance: 5%
C163 C306 = CAP POL-B: tolerance: 10%
C166 C259 C260 = CAP NP_1: tolerance: 2%
C184-C186 C190-C200 C204-C206 C216-C222 C258 = CAP NP_1: tolerance: .25pF
C187 = CAP NP_2: tolerance: 5%
C252 C255 = CAP0402
C290 C291 = CAP POL-B_10uF_10V: tolerance: 10%
C299 = CAP NP_0: tolerance: 2%
D1-D5 = LED
F1 = LITTELFUSE_0154007
F2 = FUSE/SM
FB1 FB2 FB10 FB12 FB18 FB19 FB22 FB24 FB26 FB33-FB36 FB39 FB40 = FERRITE_BEAD_0402_H
FB8 = 0805FERRITE
FB20 = FERRITE_BEAD
FB23 = FERRITE_BEAD_0603
FB28 FB30 FB31 = BEAD_NFM31P
J1 J7 = SMA-END_JACK_142-0761-801_ROUND
J2 J3 J5 J6 J11 J12 = SMA_PCB_THVT_142-0701-201_REC
J4 = CONN JACK PWR
J10 = SMP_PLUG_SMT
J13 = CON_SMVT_180POS_QTH_SAMTEC
J14 = USB_MINI_AB_MNE20-5G5P10
J15 = HEADER_2x5_100
JP1-JP3 JP5 = Jumper_1x3_100_0
JP4 = SMD_JUMPER_1x3
L1-L4 = IND0603_0: tolerance: 2%
L5 = IND0603_0: tolerance: 1%
L7 L25 L26 = IND1206
PP1 = PROBE_POINT
Q1 = PWR_MOSFET_CSD17313Q2
R1-R4 R50 R58 R59 R273-R276 = Res_0402_Zero_H_DNI
R5 R15 R43-R46 R48 R49 R53 R120-R122 R125 R129 = R_0: tolerance: 1%
R6 R25-R28 R93 R94 R103 R106 R136 R137 R175 R177 = R_5
R7 R18 R133 = Res_0402_Zero
R8 R9 R11 = RESISTOR
R10 R12 R95 R104 R148 R150 R151 R153 R157 R159 R171 R176 R221 R257 R313 = R: tolerance: 1%
R16 R17 R19-R24 = Res_0402_4.75k
R40 R88 R96 R108 R115 R117 R118 R161 R163 R165 R167 R277-R280 R289-R293 R296 R297 R302 R303 = R: tolerance: 5%
R42 R99-R101 = Res_0603: tolerance: 1%
R51 R52 R55-R57 R60 R91 R92 = Res_0402_249
R54 R61-R63 = Res_0402_22.1_H
R70 R72 R89 R90 = R_1: tolerance: 1%
R105 R130 = Res_0402_49.9: tolerance: 1%
R107 R198-R201 R206 R207 R209 R211 R213 R215 R225 R226 = R_5: tolerance: 1%
R127 R128 = RES0603: tolerance: 5%
R143 = RES0603: tolerance: 1%
R169 R174 R181 R185 = R_5: tolerance: 5%
R208 R210 R212 R214 = R_0: tolerance: 5%
SH1-SH6 = MOUNTING_HOLE
SJP1 SJP6-SJP8 = JUMPER_SMD_3POS_0402
SJP2 = SMD_JUMPER_L_0402
SJP3 = Jumper_1x3_100_430L
SJP4 SJP5 = JUMPER_SMD_1X3
SW1 SW2 = SW PUSHBUTTON_1
T1 T2 = TFMR_5_ETC1-1-13_5
TP1-TP10 TP12 TP13 TP15-TP21 = TESTLOOP_BLACK
U1 = DAC3482
U2 = TPS79633DCQ_3
U3 = FT245RL_0
U4 = EPM3032A
U5 = 25AA080A_0
U6 = LP2985_0
U7 = PE43701
U8 = SGA-7489
U11 = TPS62420_SON10_1
U12 U15 = TPS79633DCQ_1
U13 U22 = TPS79633DCQ_2
U14 U18 = TPS7A8001
U16 = LMK04806B
U21 = TPS2400
U23 = TRF3705_0
U26 = CDCV304PW_4
Y1 = OSC_6_SM_FOX_HCMOS

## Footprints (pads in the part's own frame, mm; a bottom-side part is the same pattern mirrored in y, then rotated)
0201
  rect 0.305x0.305 smd: 1(-0.305,0) 2(0.305,0)
0402
  rect 0.508x0.508 smd: 1(-0.635,0) 2(0.381,0)
0603
  rect 0.762x0.787 smd: 1(-0.787,0) 2(0.787,0)
0805
  rect 1.016x1.27 smd: 1(-1.016,0) 2(1.016,0)
1206
  rect 1.321x1.6 smd: 1(-1.524,0) 2(1.524,0)
1206_BEAD_NFM31P
  rect 1.016x1.575 smd: 1(-1.778,0) 3(1.778,0)
  rect 1.321x2.032 smd: 2(0,0)
1806
  rect 1.118x1.829 smd: 1(-1.854,0) 2(1.854,0)
1810
  rect 1.753x2.896 smd: 1(-2.629,0) 2(2.629,0)
CON_RAPC722_JACK_THVT_3
  round 4.318 hole 3.556: 1(0,3.124)
  round 3.81 hole 3.048: 2(0,-3.124) 3(4.801,0.127)
CON_SMRT_USBMNE20_F
  round 1.524 hole 1.143 unplated: (0.65,-2.2) (0.65,2.2)
  rect 2.311x0.508 smd: 1(3.45,1.6) 2(3.45,0.8) 3(3.45,0) 4(3.45,-0.8) 5(3.45,-1.6)
  rect 2.489x2.007 smd: 6(-2.15,-4.45) 7(3.35,-4.45) 8(3.35,4.45) 9(-2.15,4.45)
CON_SMVT_180POS_QTH_SAMTEC_RT1
  round 2.337 hole 1.727: (-5.123,-2.032) (63.558,-2.032)
  round 0.254 hole 1.016 unplated: (-0.03,0) (58.466,0)
  rect 0.305x1.448 smd: 1(1.958,1.054) 2(1.958,-5.118) 3(2.459,1.054) 4(2.459,-5.118) 5(2.959,1.054) 6(2.959,-5.118) 7(3.459,1.054) 8(3.459,-5.118) 9(3.96,1.054) 10(3.96,-5.118) 11(4.46,1.054) 12(4.46,-5.118) 13(4.961,1.054) 14(4.961,-5.118) 15(5.461,1.054) 16(5.461,-5.118) 17(5.961,1.054) 18(5.961,-5.118) 19(6.462,1.054) 20(6.462,-5.118) 21(6.962,1.054) 22(6.962,-5.118) 23(7.463,1.054) 24(7.463,-5.118) 25(7.963,1.054) 26(7.963,-5.118) 27(8.463,1.054) 28(8.463,-5.118) 29(8.964,1.054) 30(8.964,-5.118) 31(9.464,1.054) 32(9.464,-5.118) 33(9.964,1.054) 34(9.964,-5.118) 35(10.465,1.054) 36(10.465,-5.118) 37(10.965,1.054) 38(10.965,-5.118) 39(11.466,1.054) 40(11.466,-5.118) 41(11.966,1.054) 42(11.966,-5.118) 43(12.466,1.054) 44(12.466,-5.118) 45(12.967,1.054) 46(12.967,-5.118) 47(13.467,1.054) 48(13.467,-5.118) 49(13.967,1.054) 50(13.967,-5.118) 51(14.468,1.054) 52(14.468,-5.118) 53(14.968,1.054) 54(14.968,-5.118) 55(15.469,1.054) 56(15.469,-5.118) 57(15.969,1.054) 58(15.969,-5.118) 59(16.469,1.054) 60(16.469,-5.118) 61(21.961,1.054) 62(21.961,-5.118) 63(22.461,1.054) 64(22.461,-5.118) 65(22.962,1.054) 66(22.962,-5.118) 67(23.462,1.054) 68(23.462,-5.118) 69(23.962,1.054) 70(23.962,-5.118) 71(24.463,1.054) 72(24.463,-5.118) 73(24.963,1.054) 74(24.963,-5.118) 75(25.463,1.054) 76(25.463,-5.118) 77(25.964,1.054) 78(25.964,-5.118) 79(26.464,1.054) 80(26.464,-5.118) 81(26.965,1.054) 82(26.965,-5.118) 83(27.465,1.054) 84(27.465,-5.118) 85(27.965,1.054) 86(27.965,-5.118) 87(28.466,1.054) 88(28.466,-5.118) 89(28.966,1.054) 90(28.966,-5.118) 91(29.467,1.054) 92(29.467,-5.118) 93(29.967,1.054) 94(29.967,-5.118) 95(30.467,1.054) 96(30.467,-5.118) 97(30.968,1.054) 98(30.968,-5.118) 99(31.468,1.054) 100(31.468,-5.118) 101(31.968,1.054) 102(31.968,-5.118) 103(32.469,1.054) 104(32.469,-5.118) 105(32.969,1.054) 106(32.969,-5.118) 107(33.47,1.054) 108(33.47,-5.118) 109(33.97,1.054) 110(33.97,-5.118) 111(34.47,1.054) 112(34.47,-5.118) 113(34.971,1.054) 114(34.971,-5.118) 115(35.471,1.054) 116(35.471,-5.118) 117(35.971,1.054) 118(35.971,-5.118) 119(36.472,1.054) 120(36.472,-5.118) 121(41.963,1.054) 122(41.963,-5.118) 123(42.464,1.054) 124(42.464,-5.118) 125(42.964,1.054) 126(42.964,-5.118) 127(43.464,1.054) 128(43.464,-5.118) 129(43.965,1.054) 130(43.965,-5.118) 131(44.465,1.054) 132(44.465,-5.118) 133(44.966,1.054) 134(44.966,-5.118) 135(45.466,1.054) 136(45.466,-5.118) 137(45.966,1.054) 138(45.966,-5.118) 139(46.467,1.054) 140(46.467,-5.118) 141(46.967,1.054) 142(46.967,-5.118) 143(47.468,1.054) 144(47.468,-5.118) 145(47.968,1.054) 146(47.968,-5.118) 147(48.468,1.054) 148(48.468,-5.118) 149(48.969,1.054) 150(48.969,-5.118) 151(49.469,1.054) 152(49.469,-5.118) 153(49.969,1.054) 154(49.969,-5.118) 155(50.47,1.054) 156(50.47,-5.118) 157(50.97,1.054) 158(50.97,-5.118) 159(51.471,1.054) 160(51.471,-5.118) 161(51.971,1.054) 162(51.971,-5.118) 163(52.471,1.054) 164(52.471,-5.118) 165(52.972,1.054) 166(52.972,-5.118) 167(53.472,1.054) 168(53.472,-5.118) 169(53.972,1.054) 170(53.972,-5.118) 171(54.473,1.054) 172(54.473,-5.118) 173(54.973,1.054) 174(54.973,-5.118) 175(55.474,1.054) 176(55.474,-5.118) 177(55.974,1.054) 178(55.974,-5.118) 179(56.474,1.054) 180(56.474,-5.118)
  rect 2.54x0.635 smd: 181(0.765,-2.032) 184(17.656,-2.032) 185(20.767,-2.032) 188(37.658,-2.032) 189(40.77,-2.032) 192(57.661,-2.032)
  rect 4.699x0.635 smd: 182(6.035,-2.032) 183(12.385,-2.032) 186(26.038,-2.032) 187(32.388,-2.032) 190(46.04,-2.032) 191(52.39,-2.032)
DBV5
  rect 1.4x0.5 smd: 1(-1.1,0.95) 2(-1.1,0) 3(-1.1,-0.95) 4(1.1,-0.95) 5(1.1,0.95)
HDR_THVT_1X3_100_M
  rect 1.575x1.575 hole 1.016: 1(0,0)
  round 1.575 hole 1.016: 2(0,-2.54) 3(0,-5.08)
HDR_THVT_2X5_100_M
  rect 1.473x1.473 hole 0.965: 1(0,0)
  round 1.473 hole 0.965: 2(2.54,0) 3(0,-2.54) 4(2.54,-2.54) 5(0,-5.08) 6(2.54,-5.08) 7(0,-7.62) 8(2.54,-7.62) 9(0,-10.16) 10(2.54,-10.16)
JUMPER_SMD_3POS_0402
  rect 0.508x0.508 smd: 1(1.016,0) 2(0,0) 3(-1.016,0)
JUMPER_SMD_L_0603
  rect 0.762x0.813 smd: 1(-1.067,0) 2(0.508,0) 3(0.508,1.575)
LED_0805
  rect 1.422x1.524 smd: 1(-1.143,0) 2(1.143,0)
LPS3015
  custom 0.286x0.286 smd: 1(-1.143,0) 2(1.143,0)
MFG053_PTH
  round 1.854 hole 1.346: 1(0,0)
NANO_SMF
  rect 4.242x3.81 smd: 1(-3.186,0) 2(3.186,0)
OSC_6_SM_295X205_100_CUSTOM
  rect 1.8x2 smd: 1(-2.54,-2.095) 2(0,-2.095) 3(2.54,-2.095) 4(2.54,2.095) 5(0,2.095) 6(-2.54,2.095)
PROBE_POINT_30PAD
  round 0.762 smd: 1(0,0)
QFN_24_163X163_0P50MM_PWRPAD
  oval 0.762x0.305 smd: 1(-2.012,1.25) 2(-2.012,0.75) 3(-2.012,0.25) 4(-2.012,-0.25) 5(-2.012,-0.75) 6(-2.012,-1.25) 13(2.012,-1.25) 14(2.012,-0.75) 15(2.012,-0.25) 16(2.012,0.25) 17(2.012,0.75) 18(2.012,1.25)
  oval 0.305x0.762 smd: 7(-1.25,-2.012) 8(-0.75,-2.012) 9(-0.25,-2.012) 10(0.25,-2.012) 11(0.75,-2.012) 12(1.25,-2.012) 19(1.25,2.012) 20(0.75,2.012) 21(0.25,2.012) 22(-0.25,2.012) 23(-0.75,2.012) 24(-1.25,2.012)
  rect 2.54x2.54 smd: 25(0,0)
QFN_32_197X197_20_PWRPAD
  rect 0.762x0.33 smd: 1(-2.4,1.75) 2(-2.4,1.25) 3(-2.4,0.75) 4(-2.4,0.25) 5(-2.4,-0.25) 6(-2.4,-0.75) 7(-2.4,-1.25) 8(-2.4,-1.75) 17(2.4,-1.75) 18(2.4,-1.25) 19(2.4,-0.75) 20(2.4,-0.25) 21(2.4,0.25) 22(2.4,0.75) 23(2.4,1.25) 24(2.4,1.75)
  rect 0.33x0.762 smd: 9(-1.75,-2.4) 10(-1.25,-2.4) 11(-0.75,-2.4) 12(-0.25,-2.4) 13(0.25,-2.4) 14(0.75,-2.4) 15(1.25,-2.4) 16(1.75,-2.4) 25(1.75,2.4) 26(1.25,2.4) 27(0.75,2.4) 28(0.25,2.4) 29(-0.25,2.4) 30(-0.75,2.4) 31(-1.25,2.4) 32(-1.75,2.4)
  rect 3.099x3.099 smd: 33(0,0)
QFN_64_360X360_0P50MM_SQA64
  rect 0.6x0.24 smd: 1(-4.58,3.753) 2(-4.58,3.252) 3(-4.58,2.752) 4(-4.58,2.252) 5(-4.58,1.751) 6(-4.58,1.251) 7(-4.58,0.751) 8(-4.58,0.25) 9(-4.58,-0.25) 10(-4.58,-0.751) 11(-4.58,-1.251) 12(-4.58,-1.751) 13(-4.58,-2.252) 14(-4.58,-2.752) 15(-4.58,-3.252) 16(-4.58,-3.753) 33(4.58,-3.753) 34(4.58,-3.252) 35(4.58,-2.752) 36(4.58,-2.252) 37(4.58,-1.751) 38(4.58,-1.251) 39(4.58,-0.751) 40(4.58,-0.25) 41(4.58,0.25) 42(4.58,0.751) 43(4.58,1.251) 44(4.58,1.751) 45(4.58,2.252) 46(4.58,2.752) 47(4.58,3.252) 48(4.58,3.753)
  rect 0.24x0.6 smd: 17(-3.753,-4.58) 18(-3.252,-4.58) 19(-2.752,-4.58) 20(-2.252,-4.58) 21(-1.751,-4.58) 22(-1.251,-4.58) 23(-0.751,-4.58) 24(-0.25,-4.58) 25(0.25,-4.58) 26(0.751,-4.58) 27(1.251,-4.58) 28(1.751,-4.58) 29(2.252,-4.58) 30(2.752,-4.58) 31(3.252,-4.58) 32(3.753,-4.58) 49(3.753,4.58) 50(3.252,4.58) 51(2.752,4.58) 52(2.252,4.58) 53(1.751,4.58) 54(1.251,4.58) 55(0.751,4.58) 56(0.25,4.58) 57(-0.25,4.58) 58(-0.751,4.58) 59(-1.251,4.58) 60(-1.751,4.58) 61(-2.252,4.58) 62(-2.752,4.58) 63(-3.252,4.58) 64(-3.753,4.58)
  rect 7.188x7.188 smd: 65(0,0)
SC70_DCK_G5
  rect 0.889x0.305 smd: 1(-0.95,0.65) 2(-0.95,0) 3(-0.95,-0.65) 4(0.95,-0.65) 5(0.95,0.65)
SMA_SMEL_DUAL_PSF-S01_250X215
  rect 0.508x4.064 smd: 1(0,-2.032)
  rect 3.048x4.064 smd: 2(-3.556,-2.032) 3(3.556,-2.032) 4(-3.556,-2.032) 5(3.556,-2.032)
SMA_THRT_276X276
  round 2.261 hole 1.499: 1(0,0)
  round 2.464 hole 1.702: 2(-2.54,2.54) 3(2.54,2.54) 4(2.54,-2.54) 5(-2.54,-2.54)
SMA_THVT_320X320
  round 2.337 hole 1.575: 1(0,0)
  round 2.464 hole 1.702: 2(-2.54,2.54) 3(2.54,2.54) 4(2.54,-2.54) 5(-2.54,-2.54)
SMD_JUMPER_L_0402
  rect 0.508x0.508 smd: 1(-0.508,0) 2(0.508,0) 3(0.508,1.016)
SMP_B120
  rect 0.508x1.321 smd: 1(0,-3.1)
  custom 1.3x1.3 smd: 2(0,0)
SO_8_210X212_50
  rect 0.508x1.778 smd: 1(-1.905,-3.594) 2(-0.635,-3.594) 3(0.635,-3.594) 4(1.905,-3.594) 5(1.905,3.594) 6(0.635,3.594) 7(-0.635,3.594) 8(-1.905,3.594)
SON_8_2MMX2MM_0P65MM
  rect 0.4x0.46 smd: 1(-0.653,-0.93) 2(-0.003,-0.93) 3(0.647,-0.93) 4(0.647,0.93) 5(-0.003,0.93) 6(-0.653,0.93)
  rect 0.4x0.85 smd: 7(0.647,0.12)
  rect 1.05x1.1 smd: 8(-0.327,0)
SON_8_124X124_PWRPAD_DRB
  oval 0.838x0.279 smd: 1(-1.475,0.975) 2(-1.475,0.325) 3(-1.475,-0.325) 4(-1.475,-0.975) 5(1.475,-0.975) 6(1.475,-0.325) 7(1.475,0.325) 8(1.475,0.975)
  rect 1.651x2.388 smd: 9(0,0)
SON_DRC_10
  rect 0.864x0.305 smd: 1(-1.5,1) 2(-1.5,0.5) 3(-1.5,0) 4(-1.5,-0.5) 5(-1.5,-1) 6(1.5,-1) 7(1.5,-0.5) 8(1.5,0) 9(1.5,0.5) 10(1.5,1)
  rect 1.524x3 smd: 11(0,0)
SON_DRV_6
  rect 0.66x0.254 smd: 1(-1.152,0.65) 2(-1.152,0) 3(-1.152,-0.65) 4(1.152,-0.65) 5(1.152,0) 6(1.152,0.65)
  rect 1.016x1.626 smd: 7(0,0)
SOT_5_120X69_37
  rect 0.61x1.524 smd: 1(-0.95,-1.75) 2(0,-1.75) 3(0.95,-1.75) 4(0.95,1.75) 5(-0.95,1.75)
SOT_89_4321
  rect 0.813x1.778 smd: 1(-1.5,-1.889) 3(1.5,-1.889)
  rect 1.016x1.778 smd: 2(0,-1.889)
  rect 1.727x2.438 smd: 4(0,0.794)
SOT_223_6_TG
  rect 0.762x2.388 smd: 1(-3.175,-3.378) 2(-1.905,-3.378) 3(-0.635,-3.378) 4(0.635,-3.378) 5(1.905,-3.378)
  rect 3.81x2.286 smd: 6(-0.635,2.997)
SSOP_28_413X220_26
  rect 1.778x0.406 smd: 1(-3.625,4.225) 2(-3.625,3.575) 3(-3.625,2.925) 4(-3.625,2.275) 5(-3.625,1.625) 6(-3.625,0.975) 7(-3.625,0.325) 8(-3.625,-0.325) 9(-3.625,-0.975) 10(-3.625,-1.625) 11(-3.625,-2.275) 12(-3.625,-2.925) 13(-3.625,-3.575) 14(-3.625,-4.225) 15(3.625,-4.225) 16(3.625,-3.575) 17(3.625,-2.925) 18(3.625,-2.275) 19(3.625,-1.625) 20(3.625,-0.975) 21(3.625,-0.325) 22(3.625,0.325) 23(3.625,0.975) 24(3.625,1.625) 25(3.625,2.275) 26(3.625,2.925) 27(3.625,3.575) 28(3.625,4.225)
SW_RESET_PTS635
  round 2.032 hole 1.397: 1(-3.251,0) 2(3.251,0)
TANT_A
  rect 1.524x1.397 smd: 1(-1.283,0) 2(1.283,0)
TANT_B
  rect 1.6x2.413 smd: 1(-1.867,0) 2(1.867,0)
TESTPOINT_62DIA
  round 2.337 hole 1.575: 1(0,0)
TQFP_44_39X39_32
  round 0.762 smd: (-5.842,-5.842) (5.842,5.588)
  rect 1.778x0.457 smd: 1(-5.625,4) 2(-5.625,3.2) 3(-5.625,2.4) 4(-5.625,1.6) 5(-5.625,0.8) 6(-5.625,0) 7(-5.625,-0.8) 8(-5.625,-1.6) 9(-5.625,-2.4) 10(-5.625,-3.2) 11(-5.625,-4) 23(5.625,-4) 24(5.625,-3.2) 25(5.625,-2.4) 26(5.625,-1.6) 27(5.625,-0.8) 28(5.625,0) 29(5.625,0.8) 30(5.625,1.6) 31(5.625,2.4) 32(5.625,3.2) 33(5.625,4)
  rect 0.457x1.778 smd: 12(-4,-5.625) 13(-3.2,-5.625) 14(-2.4,-5.625) 15(-1.6,-5.625) 16(-0.8,-5.625) 17(0,-5.625) 18(0.8,-5.625) 19(1.6,-5.625) 20(2.4,-5.625) 21(3.2,-5.625) 22(4,-5.625) 34(4,5.625) 35(3.2,5.625) 36(2.4,5.625) 37(1.6,5.625) 38(0.8,5.625) 39(0,5.625) 40(-0.8,5.625) 41(-1.6,5.625) 42(-2.4,5.625) 43(-3.2,5.625) 44(-4,5.625)
TSSOP_8_177X122_26
  rect 1.778x0.406 smd: 1(-2.825,0.975) 2(-2.825,0.325) 3(-2.825,-0.325) 4(-2.825,-0.975) 5(2.825,-0.975) 6(2.825,-0.325) 7(2.825,0.325) 8(2.825,0.975)
unnamed
  round 2.286 hole 3.175 unplated: (0,0)
unnamed#3
  round 1.016 smd: 1(0,0)
WQFN_88_354X354_0P60MM
  rect 0.406x0.254 smd: A1(-4.3,3) A2(-4.3,2.4) A3(-4.3,1.8) A4(-4.3,1.2) A5(-4.3,0.6) A6(-4.3,0) A7(-4.3,-0.6) A8(-4.3,-1.2) A9(-4.3,-1.8) A10(-4.3,-2.4) A11(-4.3,-3) A23(4.3,-3) A24(4.3,-2.4) A25(4.3,-1.8) A26(4.3,-1.2) A27(4.3,-0.6) A28(4.3,0) A29(4.3,0.6) A30(4.3,1.2) A31(4.3,1.8) A32(4.3,2.4) A33(4.3,3) B1(-3.65,2.7) B2(-3.65,2.1) B3(-3.65,1.5) B4(-3.65,0.9) B5(-3.65,0.3) B6(-3.65,-0.3) B7(-3.65,-0.9) B8(-3.65,-1.5) B9(-3.65,-2.1) B10(-3.65,-2.7) B21(3.65,-2.7) B22(3.65,-2.1) B23(3.65,-1.5) B24(3.65,-0.9) B25(3.65,-0.3) B26(3.65,0.3) B27(3.65,0.9) B28(3.65,1.5) B29(3.65,2.1) B30(3.65,2.7)
  rect 0.254x0.406 smd: A12(-3,-4.3) A13(-2.4,-4.3) A14(-1.8,-4.3) A15(-1.2,-4.3) A16(-0.6,-4.3) A17(0,-4.3) A18(0.6,-4.3) A19(1.2,-4.3) A20(1.8,-4.3) A21(2.4,-4.3) A22(3,-4.3) A34(2.95,4.3) A35(2.35,4.3) A36(1.75,4.3) A37(1.15,4.3) A38(0.55,4.3) A39(-0.05,4.3) A40(-0.65,4.3) A41(-1.25,4.3) A42(-1.85,4.3) A43(-2.45,4.3) A44(-3.05,4.3) B11(-2.7,-3.65) B12(-2.1,-3.65) B13(-1.5,-3.65) B14(-0.9,-3.65) B15(-0.3,-3.65) B16(0.3,-3.65) B17(0.9,-3.65) B18(1.5,-3.65) B19(2.1,-3.65) B20(2.7,-3.65) B31(2.65,3.65) B32(2.05,3.65) B33(1.45,3.65) B34(0.85,3.65) B35(0.25,3.65) B36(-0.35,3.65) B37(-0.95,3.65) B38(-1.55,3.65) B39(-2.15,3.65) B40(-2.75,3.65)
  rect 0.889x0.889 smd: C1(-4.05,4.05) C2(-4.05,-4.05) C3(4.05,-4.05) C4(4.05,4.05)
  rect 6.299x6.299 smd: C5(0,0)
XFMR_MINICIRCUITS_AT224_1
  rect 1.651x0.762 smd: 1(-1.6,-1.905) 2(-1.6,0) 3(-1.6,1.905) 4(1.6,1.905) 5(1.6,0) 6(1.6,-1.905)

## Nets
6VIN: C143.1 C144.1 F1.2 J13.1 J13.2 J13.3 J13.4
+1.2VCLK: C38.1 C40.1 C148.1 C238.1 C242.1 FB35.2 TP19.1(TP) U1.A4(CLKVDD)
+1.2VD: C25.1 C26.1 C27.1 C29.1 C30.1 C134.1 C233.1 FB30.3 TP15.1(TP) U1.A6(DIGVDD#A6) U1.A9(DIGVDD#A9) U1.A25(DIGVDD#A25) U1.A28(DIGVDD#A28)
+1.2VDAC: C15.1 C17.1 C19.1 C36.1 C53.1 C147.1 C170.1 C243.1 FB34.2 TP18.1(TP) U1.A35(DACVDD#A35) U1.A39(DACVDD#A39) U1.A43(DACVDD#A43) U1.B4(VFUSE)
+3.3V_MOD1: FB33.2 JP1.1(PIN1) JP5.1(PIN1) R88.2 TP10.1(TP)
+3.3V_MOD2: FB36.2 R96.1 TP5.1(TP)
+3.3VA: C5.1 C6.1 C13.1 C20.1 C21.1 C22.1 C23.1 C24.1 FB1.1 FB24.2 TP16.1(TP) U1.A36(AVDD#A36) U1.A37(AVDD#A37) U1.A38(AVDD#A38) U1.A40(AVDD#A40) U1.A41(AVDD#A41) U1.A42(AVDD#A42) U1.B31(AVDD#B31)
+3.3VCLK: C72.1 C75.1 C76.1 C80.1 C81.1 C82.1 C83.1 C84.1 C85.2 C117.2 C128.1 C135.2 C138.2 C139.2 C178.1 C182.1 C250.1 C312.1 FB8.2 FB10.2 FB12.2 FB18.2 FB19.2 J15.4 JP4.1(PIN1) R70.1 R120.1 R121.2 R122.2 R125.2 R129.2 SJP2.1(PIN1) TP17.1(TP) U4.9(VCCIO#9) U4.17(VCCINT#17) U4.29(VCCIO#29) U4.41(VCCINT#41) U5.8(VCC) U15.4(OUT) U16.10(VCC1) U16.24(VCC4) U16.30(VCC5) U16.35(VCC6) U16.38(VCC7) U16.43(VCC9)
+3.3VD: C41.1 C42.1 C43.1 FB22.2 JP2.1(PIN1) JP3.1(PIN1) R46.2 TP21.1(TP) U1.A17(IOVDD#A17) U1.B6(IOVDD#B6) U1.B25(IOVDD#B25)
+3.3VRF: C115.1 C171.1 FB23.2 FB33.1 FB36.1 R107.1 R108.1 R157.2 TP4.1(TP) U14.1(OUT1) U14.2(OUT2)
+3.6V: L7.1 U2.1(SW)
+5V_MOD1: FB39.1 R209.1 R211.1 R213.1 R215.1 TP2.1(TP)
+5V_MOD2: FB40.1 R115.1 R118.1 TP1.1(TP)
+5VA_MOD: C173.1 C174.1 FB39.2 FB40.2 R176.2 R293.1 TP3.1(TP) U18.1(OUT1) U18.2(OUT2)
+6V: C9.1 C111.1 C112.1 C114.1 C120.1 C150.1 C154.1 C155.1 C161.1 C172.1 C237.1 C304.1 FB20.1 R143.2 SJP3.1(PIN1) U2.4(EN) U2.5(IN) U6.1(VIN) U11.2(MODE/DATA) U11.3(VIN) U11.7(EN1) U11.9(EN2) U14.5(EN) U14.7(IN2) U14.8(IN1) U18.5(EN) U18.7(IN2) U18.8(IN1)
GNDA: C5.2 C6.2 C7.2 C8.2 C9.2 C13.2 C15.2 C17.2 C19.2 C20.2 C21.2 C22.2 C23.2 C24.2 C25.2 C26.2 C27.2 C29.2 C30.2 C34.2 C35.2 C36.2 C38.2 C40.2 C41.2 C42.2 C43.2 C47.2 C48.2 C49.2 C50.2 C52.2 C53.2 C59.2 C63.2 C64.2 C65.2 C72.2 C75.2 C76.2 C77.1 C78.1 C80.2 C81.2 C82.2 C83.2 C84.2 C85.1 C86.2 C87.2 C88.2 C89.2 C90.2 C95.2 C96.2 C97.2 C99.2 C102.2 C107.2 C110.2 C111.2 C112.2 C113.2 C114.2 C115.2 C117.1 C119.2 C120.2 C121.1 C122.1 C128.2 C131.1 C132.1 C133.2 C134.2 C135.1 C138.1 C139.1 C143.2 C144.2 C145.2 C146.2 C147.2 C148.2 C149.2 C150.2 C152.2 C153.2 C154.2 C155.2 C156.1 C157.1 C161.2 C162.2 C163.2 C164.2 C165.2 C167.2 C169.2 C170.2 C171.2 C172.2 C173.2 C174.2 C175.2 C176.2 C178.2 C179.2 C180.2 C181.2 C182.2 C187.1 C191.2 C192.2 C193.2 C194.2 C195.1 C196.1 C197.1 C198.1 C199.1 C200.1 C215.2 C216.1 C217.1 C218.2 C219.2 C220.2 C221.2 C233.2 C234.2 C237.2 C238.2 C240.2 C242.2 C243.2 C244.2 C245.2 C246.2 C247.2 C250.2 C251.2 C252.2 C253.2 C254.2 C255.2 C256.2 C288.2 C289.2 C290.2 C291.2 C298.2 C300.2 C302.2 C303.2 C304.2 C305.2 C306.2 C307.2 C312.2 C337.2 D1.2(CATHODE) D2.2(CATHODE) D3.2(CATHODE) D4.2(CATHODE) D5.2(CATHODE) FB28.2 FB30.2 FB31.2 J1.2(GND#2) J1.3(GND#3) J1.4(GND#4) J1.5(GND#5) J2.2(SHIELD1) J2.3(SHIELD2) J2.4(SHIELD3) J2.5(SHIELD4) J3.2(SHIELD1) J3.3(SHIELD2) J3.4(SHIELD3) J3.5(SHIELD4) J4.2 J4.3 J5.2(SHIELD1) J5.3(SHIELD2) J5.4(SHIELD3) J5.5(SHIELD4) J6.2(SHIELD1) J6.3(SHIELD2) J6.4(SHIELD3) J6.5(SHIELD4) J7.2(GND#2) J7.3(GND#3) J7.4(GND#4) J7.5(GND#5) J10.2(SHIELD1) J11.2(SHIELD1) J11.3(SHIELD2) J11.4(SHIELD3) J11.5(SHIELD4) J12.2(SHIELD1) J12.3(SHIELD2) J12.4(SHIELD3) J12.5(SHIELD4) J13.7 J13.8 J13.9 J13.10 J13.65 J13.66 J13.71 J13.72 J13.77 J13.78 J13.83 J13.84 J13.89 J13.90 J13.95 J13.96 J13.101 J13.102 J13.107 J13.108 J13.113 J13.114 J13.119 J13.120 J13.125 J13.126 J13.131 J13.132 J13.137 J13.138 J13.143 J13.144 J13.149 J13.150 J13.155 J13.156 J13.161 J13.162 J13.167 J13.168 J13.173 J13.174 J13.179 J13.180 J13.181(GND#181) J13.182(GND#182) J13.183(GND#183) J13.184(GND#184) J13.185(GND#185) J13.186(GND#186) J13.187(GND#187) J13.188(GND#188) J13.189(GND#189) J13.190(GND#190) J13.191(GND#191) J13.192(GND#192) J14.5(GND) J14.6(GND1) J14.7(GND2) J14.8(GND3) J14.9(GND4) J15.2 J15.10 JP1.3(PIN3) JP2.3(PIN3) JP3.3(PIN3) JP4.3(PIN3) JP5.3(PIN3) R6.2 R10.1 R12.1 R16.2 R17.2 R19.2 R20.2 R21.2 R22.2 R23.2 R24.2 R42.2 R45.2 R51.2 R52.2 R55.2 R56.2 R57.2 R60.2 R62.1 R72.2 R89.2 R90.2 R91.2 R92.2 R93.1 R95.1 R99.2 R100.2 R101.2 R105.2 R106.1 R117.2 R130.2 R136.1 R137.1 R151.1 R153.1 R159.1 R171.1 R198.2 R199.2 R200.2 R201.2 R206.2 R207.1 R225.1 R226.2 R274.1 R313.2 SH1.1 SH2.1 SH3.1 SH4.1 SH5.1 SH6.1 SJP2.3(PIN3) SJP3.3(PIN3) SW1.1 SW2.1 T1.2 T1.5 T2.2 T2.5 TP6.1(TP) TP7.1(TP) TP8.1(TP) TP9.1(TP) TP13.1(TP) U1.B32(GND#B32) U1.B33(GND#B33) U1.B38(GND#B38) U1.B39(GND#B39) U1.C1(GND#C1) U1.C2(GND#C2) U1.C3(GND#C3) U1.C4(GND#C4) U1.C5(PWR_PAD) U2.2(MODE) U2.6(GND) U2.7(THERMPAD) U3.7(GND#7) U3.18(GND#18) U3.21(GND#21) U3.25(AGND) U3.26(TEST) U4.4(GNDIO#4) U4.11(GNDIO#11) U4.16(GNDINT#16) U4.24(GNDIO#24) U4.30(GNDIO#30) U4.36(GNDINT#36) U5.4(VSS) U6.2(GND) U7.5(GND#5) U7.6(GND#6) U7.8(GND#8) U7.9(GND#9) U7.10(GND#10) U7.11(GND#11) U7.12(GND#12) U7.13(GND#13) U7.14(GND#14) U7.15(GND#15) U7.16(GND#16) U7.17(GND#17) U7.19(GND#19) U7.20(GND#20) U7.21(A2) U7.33(PADDLE) U8.2(GND#2) U8.4(GND#4) U11.8(GND) U11.11(THERMPAD) U12.3(GND#3) U12.6(GND#6) U13.2(GND) U14.4(GND) U14.9(PAD) U15.3(GND#3) U15.6(GND#6) U16.23(GND) U16.65(DAP) U18.4(GND) U18.9(PAD) U21.2(GND) U22.2(GND) U23.2(GND#2) U23.5(GND#5) U23.7(GND#7) U23.8(GND#8) U23.11(GND#11) U23.12(GND#12) U23.13(GND#13) U23.14(GND#14) U23.15(GND#15) U23.17(GND#17) U23.19(GND#19) U23.20(GND#20) U23.23(GND#23) U23.25(THERMPAD) U26.4(GND) Y1.3(GND)
ALARM: PP1.1 U1.B29(ALARM)
ATT_LE: U4.3(IO5) U7.23(LE)
CLKIN0N: C100.2 U16.29(CLKIN0N)
CLKIN0P: C101.2 U16.28(CLKIN0P)
CLKIN1P: C79.2 U16.25(CLKIN1P/FBCLKINP/FINP)
CLKOUT0N: J3.1(CENTER) R59.1
CLKOUT0P: J2.1(CENTER) R58.1
CLKOUT6P: J5.1(CENTER) R50.1
CLKOUT8N: R91.1 R276.1 U16.54(CLKOUT8N)
CLKOUT8P: R55.1 R275.1 U16.53(CLKOUT8P)
CLKOUT_0N: R56.1 R59.2 U16.2(CLKOUT0N)
CLKOUT_0P: R57.1 R58.2 U16.1(CLKOUT0P)
CLKOUT_6P: R50.2 U16.48(CLKOUT6P)
CLOCK1: C79.1 R63.2 R105.1
CLOCKIN: J12.1(CENTER) R63.1 R130.1
CP1: C177.1 C300.1 R273.1 U16.34(CPOUT1)
CPLD_CLK: R53.1 SJP4.3(PIN3)
DA0N: J13.165 U1.A27(D0N)
DA0P: J13.163 U1.B24(D0P)
DA1N: J13.159 U1.A26(D1N)
DA1P: J13.157 U1.B23(D1P)
DA2N: J13.153 U1.B22(D2N)
DA2P: J13.151 U1.A24(D2P)
DA3N: J13.147 U1.B21(D3N)
DA3P: J13.145 U1.A23(D3P)
DA4N: J13.141 U1.A22(D4N)
DA4P: J13.139 U1.B20(D4P)
DA5N: J13.135 U1.A21(D5N)
DA5P: J13.133 U1.B19(D5P)
DA6N: J13.129 U1.A20(D6N)
DA6P: J13.127 U1.B18(D6P)
DA7N: J13.123 U1.A19(D7N)
DA7P: J13.121 U1.B17(D7P)
DA8N: J13.111 U1.B14(D8N)
DA8P: J13.109 U1.A15(D8P)
DA9N: J13.105 U1.B13(D9N)
DA9P: J13.103 U1.A14(D9P)
DA10N: J13.99 U1.B12(D10N)
DA10P: J13.97 U1.A13(D10P)
DA11N: J13.93 U1.B11(D11N)
DA11P: J13.91 U1.A12(D11P)
DA12N: J13.87 U1.A11(D12N)
DA12P: J13.85 U1.B10(D12P)
DA13N: J13.81 U1.A10(D13N)
DA13P: J13.79 U1.B9(D13P)
DA14N: J13.75 U1.B8(D14N)
DA14P: J13.73 U1.A8(D14P)
DA15N: J13.69 U1.B7(D15N)
DA15P: J13.67 U1.A7(D15P)
DAC_ALARM_SDO: U1.B27(SDO) U4.10(IO9)
DAC_FIFO_OSTR: C2.2 R5.2 U1.A2(OSTRP)
DAC_FIFO_OSTRC: C1.2 R5.1 U1.B2(OSTRN)
DAC_GPIO_0: J13.49 U4.5(IO6)
DAC_GPIO_1: J13.55 U4.6(IO7)
DAC_GPIO_2: J13.57 U4.8(IO8)
DAC_RESET: C47.1 R7.1 R46.1 SW1.2 U1.B30(RESETB)
DAC_RST: J13.48 R7.2
DAC_SPI_EN: U1.B28(SDENB) U4.25(IO20)
DACCLK: C4.2 R51.1 U16.16(CLKOUT3P)
DACCLKC: C3.2 R52.1 U16.15(CLKOUT3N)
DATACLK-N: J13.117 SJP8.2(PIN2)
DATACLK-P: J13.115 SJP7.2(PIN2)
DATACLKN: SJP1.2(PIN2) U1.B15(DATACLKN)
DATACLKP: SJP6.2(PIN2) U1.A16(DATACLKP)
DCLK-N: SJP1.1(PIN1) SJP8.1(PIN1)
DCLK-P: SJP6.1(PIN1) SJP7.1(PIN1)
DCLKN: SJP1.3(PIN3) SJP8.3(PIN3)
DCLKP: SJP6.3(PIN3) SJP7.3(PIN3)
EXTIO: C337.1 U1.A34(EXTIO)
FIFO_ISTRN: J13.178 U1.A18(FRAMEN)
FIFO_ISTRP: J13.176 U1.B16(FRAMEP)
FIFO_OSTR: C2.1 R92.1 U16.20(CLKOUT4N)
FIFO_OSTRC: C1.1 R60.1 U16.19(CLKOUT4P)
FPGA_CLKOUTN: J13.118 R276.2
FPGA_CLKOUTP: J13.116 R275.2
GAIN_SEL: R181.2 U4.28(IO18)
GC1: C187.2 JP1.2(PIN2) R181.1 U23.6(GC)
IN1: C125.1 C227.2 R207.2 R210.2 R211.2 U23.22(BBIM)
IN-1: C227.1 R199.1 R210.1 R290.2 T1.6(PRIMARY_DOT)
IN_1: C190.2 C194.1 R290.1 R297.2 T1.1(SECONDARY_DOT)
IOUTB1: C204.1 C216.2 L1.2 R42.1 U1.B34(IOUTC2)
IOUTB2: C204.2 C219.1 L2.2 R99.1 U1.B35(IOUTC1)
IOUTC1: C185.1 C196.2 L3.2 R100.1 U1.B37(IOUTB2)
IOUTC2: C185.2 C191.1 L4.2 R101.1 U1.B36(IOUTB1)
IP1: C125.2 C214.2 R206.1 R208.2 R209.2 U23.21(BBIP)
IP-1: C214.1 R198.1 R208.1 R289.2 T1.4(PRIMARY)
IP_1: C190.1 C195.2 R289.1 R296.2 T1.3(SECONDARY)
LMK_SPI_CLK: U4.13(IO11) U16.45(CLKUWIRE)
LMK_SPI_EN: U4.12(IO10) U16.44(LEUWIRE)
LMK_SPI_MISO: U4.14(IO12) U16.27(STATUS_HOLDOVER)
LMK_SPI_MOSI: U4.15(IO13) U16.46(DATAUWIRE)
LO_P1: C121.2 C260.2 R169.1
LO_P3: C260.1 J1.1(CENTER)
LON1: C131.2 R174.2 U23.4(LON)
LOP1: C122.2 R169.2 U23.3(LOP)
MOD_PD: R185.2 U4.27(IO19)
OSC: C301.2 SJP5.1(PIN1)
OSC_IN: C60.2 U16.36(OSCINP)
OSCIN: C301.1 J11.1(CENTER)
PARITYN: J13.172 U1.A29(PARITYN)
PARITYP: J13.170 U1.B26(PARITYP)
PD1: JP5.2(PIN2) R185.1 U23.1(PD)
PLLAVDD: C48.1 C49.1 FB1.2 U1.B1(PLLAVDD)
PRI_DAC_CLKN: C100.1 J13.63
PRI_DAC_CLKP: C101.1 J13.61
PWR_IN: F1.1 F2.1 J4.1 Q1.1(D1) Q1.2(D2) Q1.5(D5) Q1.6(D6) Q1.8(D8) TP12.1(TP) U21.5(VIN)
QN1: C126.1 C229.2 R214.2 R215.2 R225.2 U23.9(BBQM)
QN-1: C229.1 R201.1 R214.1 R292.2 T2.4(PRIMARY)
QN_1: C218.1 C222.2 R292.1 R303.2 T2.3(SECONDARY)
QP1: C126.2 C228.2 R212.2 R213.2 R226.1 U23.10(BBQP)
QP-1: C228.1 R200.1 R212.1 R291.2 T2.6(PRIMARY_DOT)
QP_1: C199.2 C222.1 R291.1 R302.2 T2.1(SECONDARY_DOT)
REFIN: C60.1 R48.1
REFINN: R48.2 U26.5(X1Y1)
REFOUT: R49.2 U26.7(X1Y2)
REFOUT1: J6.1(CENTER) R49.1
REFOUT3: R53.2 U26.8(X1Y3)
RF1: C157.2 R165.2 R167.1
RF-1: C258.1 R163.1 U23.16(RFOUT)
RF_1: C156.2 C258.2 R167.2
RF_OUT1: R103.1 R136.2 R163.2
RF_OUT_1: R94.2 R106.2 R161.2
RFOUT1: J7.1(CENTER) R161.1 R165.1
ROUT: C257.2 R103.2 R137.2
ROUT1: C257.1 U8.1(RFIN)
ROUT2: C249.2 L5.2 U8.3(RFOUT)
ROUT3: C249.1 U7.7(RF1)
ROUT4: R93.2 R94.1 U7.18(RF2)
SPI_CLK: U1.A31(SCLK) U4.33(IO16) U5.6(SCK) U7.24(CLK)
SPI_DATA: U1.A30(SDIO) U4.31(IO17) U5.5(SI) U7.25(SI)
SYNC: J10.1(CENTER) U16.6(SYNC)
SYNCN: R177.2 U1.B5(SYNCN)
SYNCP: R175.2 U1.A5(SYNCP)
TCK: J15.1 R122.1 U4.26(I/O/TCK)
TDI: J15.9 R129.1 U4.1(I/O/TDI)
TDO: J15.3 R121.1 U4.32(I/O/TDO)
TMS: J15.5 R125.1 U4.7(I/O/TMS)
TXCCLKN: C3.1 R15.2 U1.B3(DACCLKN)
TXCCLKP: C4.1 R15.1 U1.A3(DACCLKP)
TXEN: J13.27 R18.2
TXENABLE: JP2.2(PIN2) R18.1 U1.A32(TXENABLE)
TXSP1: J13.26 SJP4.1(PIN1)
TXSP2: J13.28 U4.39(INPUT/GCLRN)
TXSP3: R2.2 R25.1 U4.20(IO24)
TXSP4: R3.2 R26.1 U4.21(IO23)
TXSP5: R4.2 R28.1 U4.38(INPUT/OE1)
TXSP6: R1.2 R27.1 U4.40(INPUT/OE2/GCLK2)
